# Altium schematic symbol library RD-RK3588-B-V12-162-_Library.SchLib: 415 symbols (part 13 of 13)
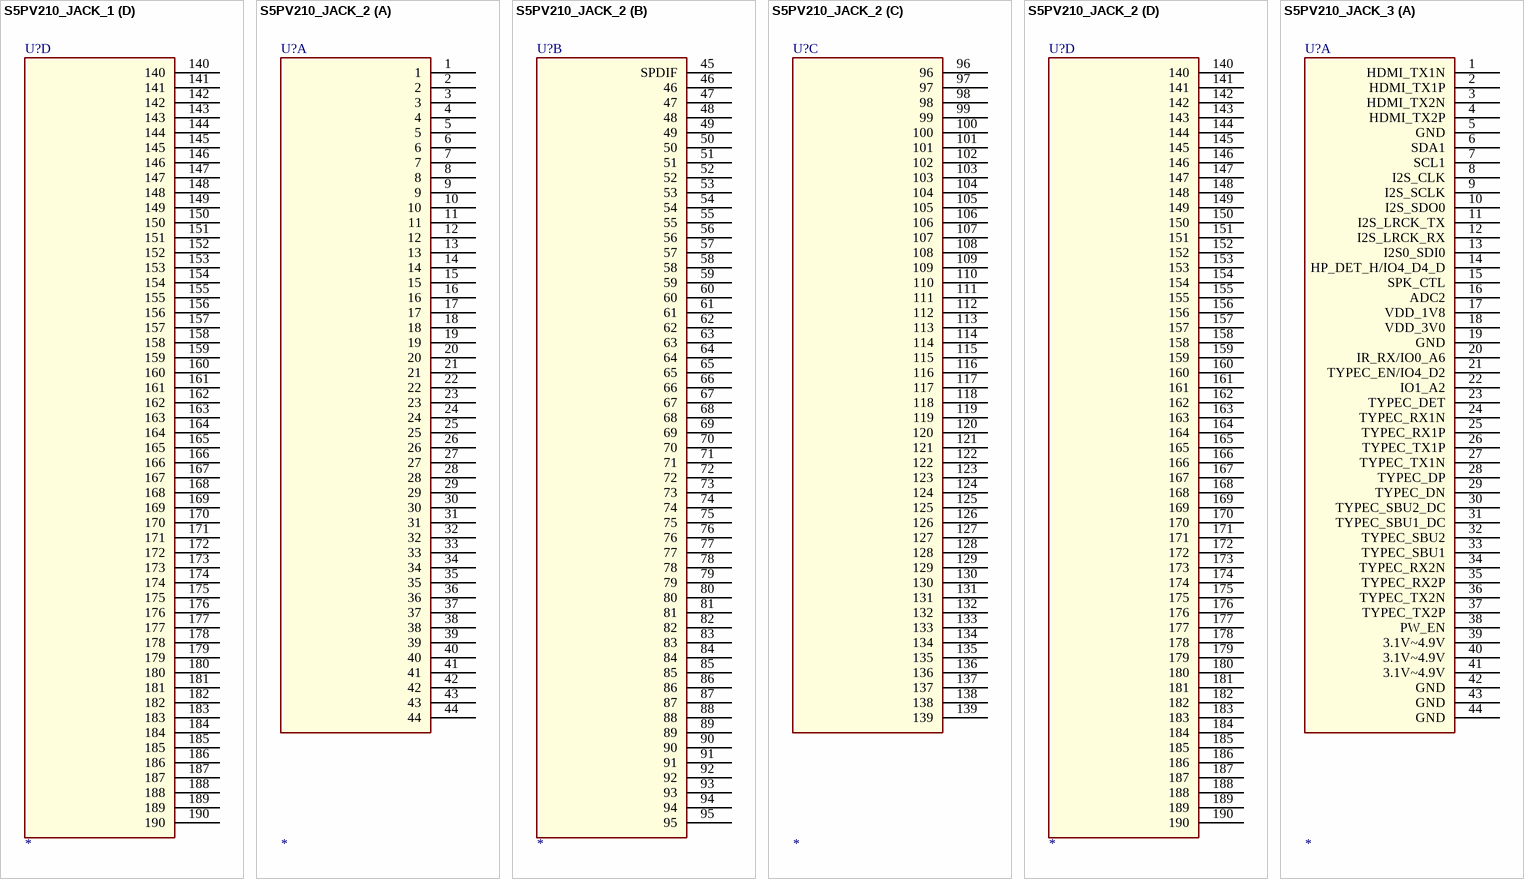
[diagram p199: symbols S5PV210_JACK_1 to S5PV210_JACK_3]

## S5PV210_JACK_1
designator U?
footprint S5PV210_JACK
part A pins: 1, 2, 3, 4, 5, 6, 7, 8, 9, 10, 11, 12, 13, 14, 15, 16, 17, 18, 19, 20, 21, 22, 23, 24, 25, 26, 27, 28, 29, 30, 31, 32, 33, 34, 35, 36, 37, 38, 39, 40, 41, 42, 43, 44
part B pins: 45, 46, 47, 48, 49, 50, 51, 52, 53, 54, 55, 56, 57, 58, 59, 60, 61, 62, 63, 64, 65, 66, 67, 68, 69, 70, 71, 72, 73, 74, 75, 76, 77, 78, 79, 80, 81, 82, 83, 84, 85, 86, 87, 88, 89, 90, 91, 92, 93, 94, 95
part C pins: 96, 97, 98, 99, 100, 101, 102, 103, 104, 105, 106, 107, 108, 109, 110, 111, 112, 113, 114, 115, 116, 117, 118, 119, 120, 121, 122, 123, 124, 125, 126, 127, 128, 129, 130, 131, 132, 133, 134, 135, 136, 137, 138, 139
part D pins: 140, 141, 142, 143, 144, 145, 146, 147, 148, 149, 150, 151, 152, 153, 154, 155, 156, 157, 158, 159, 160, 161, 162, 163, 164, 165, 166, 167, 168, 169, 170, 171, 172, 173, 174, 175, 176, 177, 178, 179, 180, 181, 182, 183, 184, 185, 186, 187, 188, 189, 190

## S5PV210_JACK_2
designator U?
footprint S5PV210_JACK
part A pins: 1, 2, 3, 4, 5, 6, 7, 8, 9, 10, 11, 12, 13, 14, 15, 16, 17, 18, 19, 20, 21, 22, 23, 24, 25, 26, 27, 28, 29, 30, 31, 32, 33, 34, 35, 36, 37, 38, 39, 40, 41, 42, 43, 44
part B pins: 45 SPDIF, 46, 47, 48, 49, 50, 51, 52, 53, 54, 55, 56, 57, 58, 59, 60, 61, 62, 63, 64, 65, 66, 67, 68, 69, 70, 71, 72, 73, 74, 75, 76, 77, 78, 79, 80, 81, 82, 83, 84, 85, 86, 87, 88, 89, 90, 91, 92, 93, 94, 95
part C pins: 96, 97, 98, 99, 100, 101, 102, 103, 104, 105, 106, 107, 108, 109, 110, 111, 112, 113, 114, 115, 116, 117, 118, 119, 120, 121, 122, 123, 124, 125, 126, 127, 128, 129, 130, 131, 132, 133, 134, 135, 136, 137, 138, 139
part D pins: 140, 141, 142, 143, 144, 145, 146, 147, 148, 149, 150, 151, 152, 153, 154, 155, 156, 157, 158, 159, 160, 161, 162, 163, 164, 165, 166, 167, 168, 169, 170, 171, 172, 173, 174, 175, 176, 177, 178, 179, 180, 181, 182, 183, 184, 185, 186, 187, 188, 189, 190

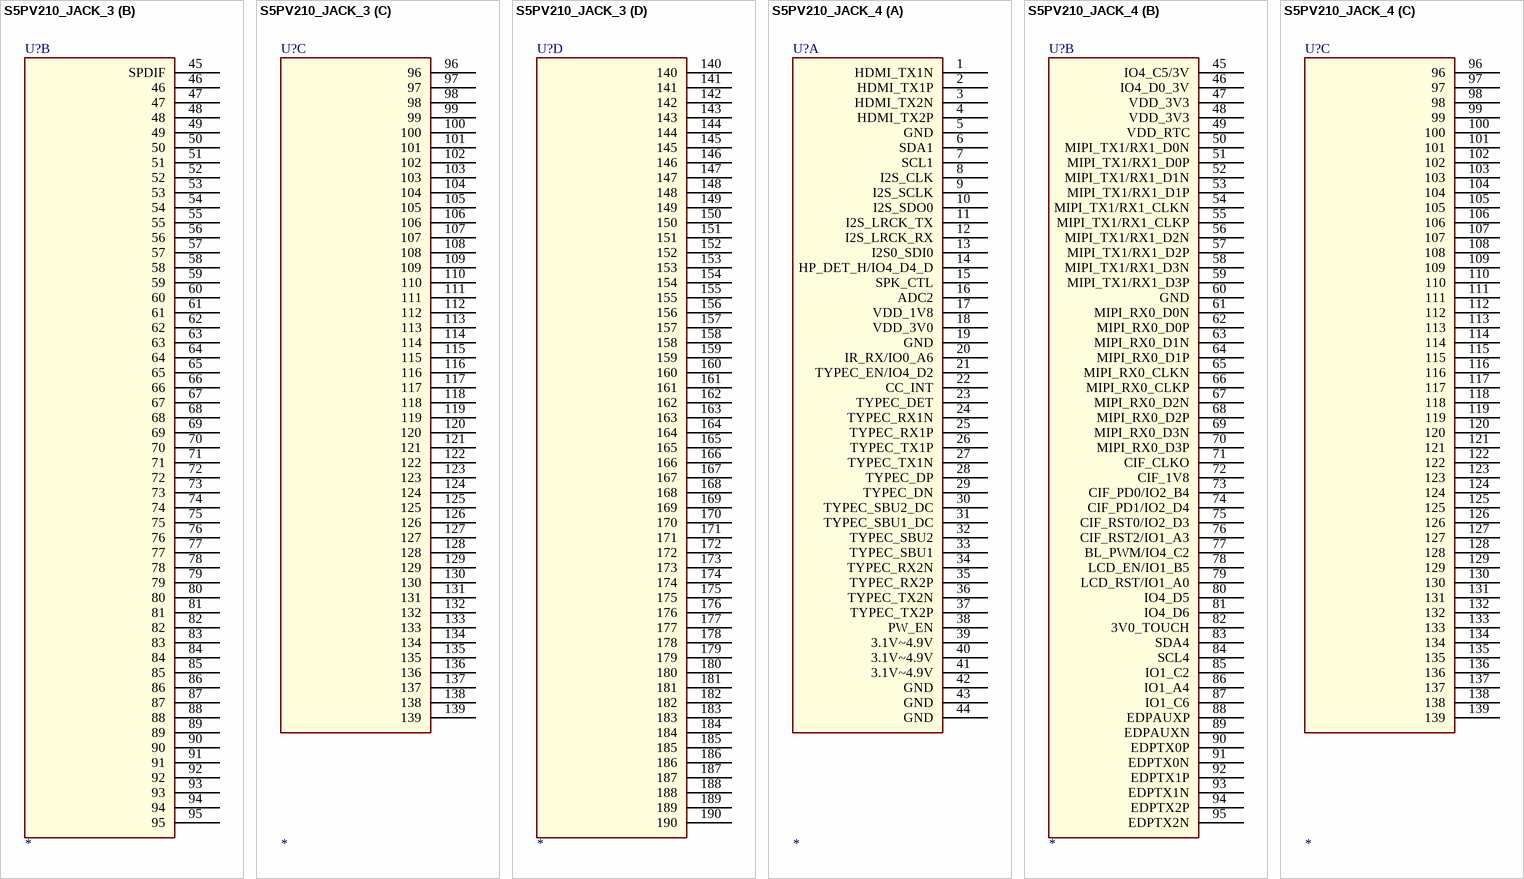
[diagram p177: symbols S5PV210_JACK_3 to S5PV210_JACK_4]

## S5PV210_JACK_3
designator U?
footprint S5PV210_JACK
part A pins: 1 HDMI_TX1N, 2 HDMI_TX1P, 3 HDMI_TX2N, 4 HDMI_TX2P, 5 GND (power), 6 SDA1, 7 SCL1, 8 I2S_CLK, 9 I2S_SCLK, 10 I2S_SDO0, 11 I2S_LRCK_TX, 12 I2S_LRCK_RX, 13 I2S0_SDI0, 14 HP_DET_H/IO4_D4_D, 15 SPK_CTL, 16 ADC2, 17 VDD_1V8, 18 VDD_3V0, 19 GND (power), 20 IR_RX/IO0_A6, 21 TYPEC_EN/IO4_D2, 22 IO1_A2, 23 TYPEC_DET, 24 TYPEC_RX1N, 25 TYPEC_RX1P, 26 TYPEC_TX1P, 27 TYPEC_TX1N, 28 TYPEC_DP, 29 TYPEC_DN, 30 TYPEC_SBU2_DC, 31 TYPEC_SBU1_DC, 32 TYPEC_SBU2, 33 TYPEC_SBU1, 34 TYPEC_RX2N, 35 TYPEC_RX2P, 36 TYPEC_TX2N, 37 TYPEC_TX2P, 38 PW_EN, 39 3.1V~4.9V (power), 40 3.1V~4.9V (power), 41 3.1V~4.9V (power), 42 GND (power), 43 GND (power), 44 GND (power)
part B pins: 45 SPDIF, 46, 47, 48, 49, 50, 51, 52, 53, 54, 55, 56, 57, 58, 59, 60, 61, 62, 63, 64, 65, 66, 67, 68, 69, 70, 71, 72, 73, 74, 75, 76, 77, 78, 79, 80, 81, 82, 83, 84, 85, 86, 87, 88, 89, 90, 91, 92, 93, 94, 95
part C pins: 96, 97, 98, 99, 100, 101, 102, 103, 104, 105, 106, 107, 108, 109, 110, 111, 112, 113, 114, 115, 116, 117, 118, 119, 120, 121, 122, 123, 124, 125, 126, 127, 128, 129, 130, 131, 132, 133, 134, 135, 136, 137, 138, 139
part D pins: 140, 141, 142, 143, 144, 145, 146, 147, 148, 149, 150, 151, 152, 153, 154, 155, 156, 157, 158, 159, 160, 161, 162, 163, 164, 165, 166, 167, 168, 169, 170, 171, 172, 173, 174, 175, 176, 177, 178, 179, 180, 181, 182, 183, 184, 185, 186, 187, 188, 189, 190

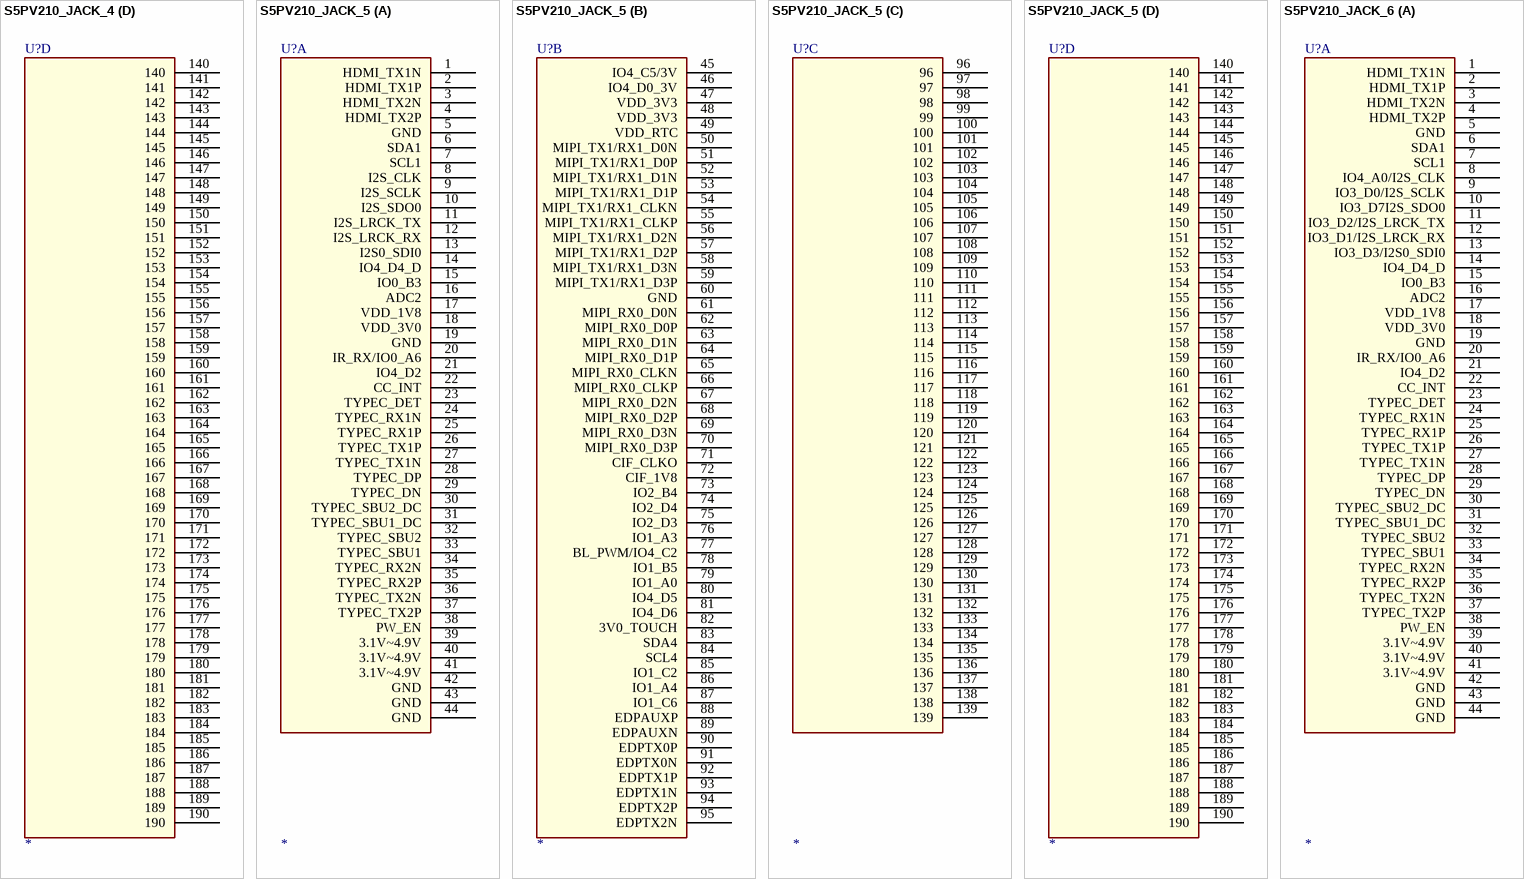
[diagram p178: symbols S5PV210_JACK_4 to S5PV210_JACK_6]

## S5PV210_JACK_4
designator U?
footprint S5PV210_JACK
part A pins: 1 HDMI_TX1N, 2 HDMI_TX1P, 3 HDMI_TX2N, 4 HDMI_TX2P, 5 GND (power), 6 SDA1, 7 SCL1, 8 I2S_CLK, 9 I2S_SCLK, 10 I2S_SDO0, 11 I2S_LRCK_TX, 12 I2S_LRCK_RX, 13 I2S0_SDI0, 14 HP_DET_H/IO4_D4_D, 15 SPK_CTL, 16 ADC2, 17 VDD_1V8, 18 VDD_3V0, 19 GND (power), 20 IR_RX/IO0_A6, 21 TYPEC_EN/IO4_D2, 22 CC_INT, 23 TYPEC_DET, 24 TYPEC_RX1N, 25 TYPEC_RX1P, 26 TYPEC_TX1P, 27 TYPEC_TX1N, 28 TYPEC_DP, 29 TYPEC_DN, 30 TYPEC_SBU2_DC, 31 TYPEC_SBU1_DC, 32 TYPEC_SBU2, 33 TYPEC_SBU1, 34 TYPEC_RX2N, 35 TYPEC_RX2P, 36 TYPEC_TX2N, 37 TYPEC_TX2P, 38 PW_EN, 39 3.1V~4.9V (power), 40 3.1V~4.9V (power), 41 3.1V~4.9V (power), 42 GND (power), 43 GND (power), 44 GND (power)
part B pins: 45 IO4_C5/3V, 46 IO4_D0_3V, 47 VDD_3V3 (power), 48 VDD_3V3 (power), 49 VDD_RTC, 50 MIPI_TX1/RX1_D0N, 51 MIPI_TX1/RX1_D0P, 52 MIPI_TX1/RX1_D1N, 53 MIPI_TX1/RX1_D1P, 54 MIPI_TX1/RX1_CLKN, 55 MIPI_TX1/RX1_CLKP, 56 MIPI_TX1/RX1_D2N, 57 MIPI_TX1/RX1_D2P, 58 MIPI_TX1/RX1_D3N, 59 MIPI_TX1/RX1_D3P, 60 GND, 61 MIPI_RX0_D0N, 62 MIPI_RX0_D0P, 63 MIPI_RX0_D1N, 64 MIPI_RX0_D1P, 65 MIPI_RX0_CLKN, 66 MIPI_RX0_CLKP, 67 MIPI_RX0_D2N, 68 MIPI_RX0_D2P, 69 MIPI_RX0_D3N, 70 MIPI_RX0_D3P, 71 CIF_CLKO, 72 CIF_1V8, 73 CIF_PD0/IO2_B4, 74 CIF_PD1/IO2_D4, 75 CIF_RST0/IO2_D3, 76 CIF_RST2/IO1_A3, 77 BL_PWM/IO4_C2, 78 LCD_EN/IO1_B5, 79 LCD_RST/IO1_A0, 80 IO4_D5, 81 IO4_D6, 82 3V0_TOUCH, 83 SDA4, 84 SCL4, 85 IO1_C2, 86 IO1_A4, 87 IO1_C6, 88 EDPAUXP, 89 EDPAUXN, 90 EDPTX0P, 91 EDPTX0N, 92 EDPTX1P, 93 EDPTX1N, 94 EDPTX2P, 95 EDPTX2N
part C pins: 96, 97, 98, 99, 100, 101, 102, 103, 104, 105, 106, 107, 108, 109, 110, 111, 112, 113, 114, 115, 116, 117, 118, 119, 120, 121, 122, 123, 124, 125, 126, 127, 128, 129, 130, 131, 132, 133, 134, 135, 136, 137, 138, 139
part D pins: 140, 141, 142, 143, 144, 145, 146, 147, 148, 149, 150, 151, 152, 153, 154, 155, 156, 157, 158, 159, 160, 161, 162, 163, 164, 165, 166, 167, 168, 169, 170, 171, 172, 173, 174, 175, 176, 177, 178, 179, 180, 181, 182, 183, 184, 185, 186, 187, 188, 189, 190

## S5PV210_JACK_5
designator U?
footprint S5PV210_JACK
part A pins: 1 HDMI_TX1N, 2 HDMI_TX1P, 3 HDMI_TX2N, 4 HDMI_TX2P, 5 GND (power), 6 SDA1, 7 SCL1, 8 I2S_CLK, 9 I2S_SCLK, 10 I2S_SDO0, 11 I2S_LRCK_TX, 12 I2S_LRCK_RX, 13 I2S0_SDI0, 14 IO4_D4_D, 15 IO0_B3, 16 ADC2, 17 VDD_1V8, 18 VDD_3V0, 19 GND (power), 20 IR_RX/IO0_A6, 21 IO4_D2, 22 CC_INT, 23 TYPEC_DET, 24 TYPEC_RX1N, 25 TYPEC_RX1P, 26 TYPEC_TX1P, 27 TYPEC_TX1N, 28 TYPEC_DP, 29 TYPEC_DN, 30 TYPEC_SBU2_DC, 31 TYPEC_SBU1_DC, 32 TYPEC_SBU2, 33 TYPEC_SBU1, 34 TYPEC_RX2N, 35 TYPEC_RX2P, 36 TYPEC_TX2N, 37 TYPEC_TX2P, 38 PW_EN, 39 3.1V~4.9V (power), 40 3.1V~4.9V (power), 41 3.1V~4.9V (power), 42 GND (power), 43 GND (power), 44 GND (power)
part B pins: 45 IO4_C5/3V, 46 IO4_D0_3V, 47 VDD_3V3 (power), 48 VDD_3V3 (power), 49 VDD_RTC, 50 MIPI_TX1/RX1_D0N, 51 MIPI_TX1/RX1_D0P, 52 MIPI_TX1/RX1_D1N, 53 MIPI_TX1/RX1_D1P, 54 MIPI_TX1/RX1_CLKN, 55 MIPI_TX1/RX1_CLKP, 56 MIPI_TX1/RX1_D2N, 57 MIPI_TX1/RX1_D2P, 58 MIPI_TX1/RX1_D3N, 59 MIPI_TX1/RX1_D3P, 60 GND, 61 MIPI_RX0_D0N, 62 MIPI_RX0_D0P, 63 MIPI_RX0_D1N, 64 MIPI_RX0_D1P, 65 MIPI_RX0_CLKN, 66 MIPI_RX0_CLKP, 67 MIPI_RX0_D2N, 68 MIPI_RX0_D2P, 69 MIPI_RX0_D3N, 70 MIPI_RX0_D3P, 71 CIF_CLKO, 72 CIF_1V8, 73 IO2_B4, 74 IO2_D4, 75 IO2_D3, 76 IO1_A3, 77 BL_PWM/IO4_C2, 78 IO1_B5, 79 IO1_A0, 80 IO4_D5, 81 IO4_D6, 82 3V0_TOUCH, 83 SDA4, 84 SCL4, 85 IO1_C2, 86 IO1_A4, 87 IO1_C6, 88 EDPAUXP, 89 EDPAUXN, 90 EDPTX0P, 91 EDPTX0N, 92 EDPTX1P, 93 EDPTX1N, 94 EDPTX2P, 95 EDPTX2N
part C pins: 96, 97, 98, 99, 100, 101, 102, 103, 104, 105, 106, 107, 108, 109, 110, 111, 112, 113, 114, 115, 116, 117, 118, 119, 120, 121, 122, 123, 124, 125, 126, 127, 128, 129, 130, 131, 132, 133, 134, 135, 136, 137, 138, 139
part D pins: 140, 141, 142, 143, 144, 145, 146, 147, 148, 149, 150, 151, 152, 153, 154, 155, 156, 157, 158, 159, 160, 161, 162, 163, 164, 165, 166, 167, 168, 169, 170, 171, 172, 173, 174, 175, 176, 177, 178, 179, 180, 181, 182, 183, 184, 185, 186, 187, 188, 189, 190

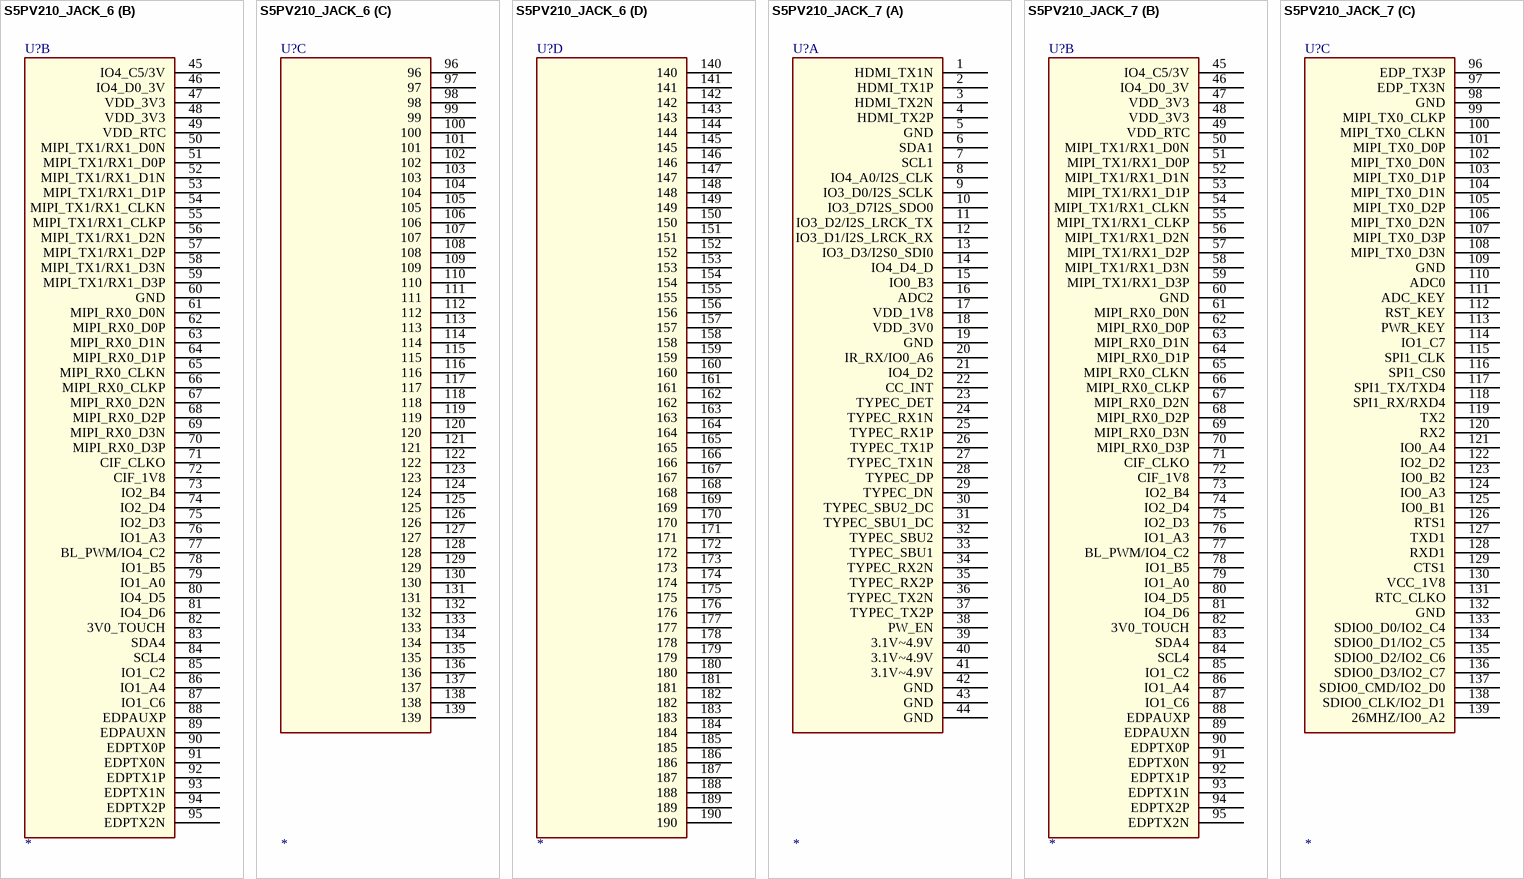
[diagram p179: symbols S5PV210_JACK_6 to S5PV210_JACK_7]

## S5PV210_JACK_6
designator U?
footprint S5PV210_JACK
part A pins: 1 HDMI_TX1N, 2 HDMI_TX1P, 3 HDMI_TX2N, 4 HDMI_TX2P, 5 GND (power), 6 SDA1, 7 SCL1, 8 IO4_A0/I2S_CLK, 9 IO3_D0/I2S_SCLK, 10 IO3_D7I2S_SDO0, 11 IO3_D2/I2S_LRCK_TX, 12 IO3_D1/I2S_LRCK_RX, 13 IO3_D3/I2S0_SDI0, 14 IO4_D4_D, 15 IO0_B3, 16 ADC2, 17 VDD_1V8, 18 VDD_3V0, 19 GND (power), 20 IR_RX/IO0_A6, 21 IO4_D2, 22 CC_INT, 23 TYPEC_DET, 24 TYPEC_RX1N, 25 TYPEC_RX1P, 26 TYPEC_TX1P, 27 TYPEC_TX1N, 28 TYPEC_DP, 29 TYPEC_DN, 30 TYPEC_SBU2_DC, 31 TYPEC_SBU1_DC, 32 TYPEC_SBU2, 33 TYPEC_SBU1, 34 TYPEC_RX2N, 35 TYPEC_RX2P, 36 TYPEC_TX2N, 37 TYPEC_TX2P, 38 PW_EN, 39 3.1V~4.9V (power), 40 3.1V~4.9V (power), 41 3.1V~4.9V (power), 42 GND (power), 43 GND (power), 44 GND (power)
part B pins: 45 IO4_C5/3V, 46 IO4_D0_3V, 47 VDD_3V3 (power), 48 VDD_3V3 (power), 49 VDD_RTC, 50 MIPI_TX1/RX1_D0N, 51 MIPI_TX1/RX1_D0P, 52 MIPI_TX1/RX1_D1N, 53 MIPI_TX1/RX1_D1P, 54 MIPI_TX1/RX1_CLKN, 55 MIPI_TX1/RX1_CLKP, 56 MIPI_TX1/RX1_D2N, 57 MIPI_TX1/RX1_D2P, 58 MIPI_TX1/RX1_D3N, 59 MIPI_TX1/RX1_D3P, 60 GND, 61 MIPI_RX0_D0N, 62 MIPI_RX0_D0P, 63 MIPI_RX0_D1N, 64 MIPI_RX0_D1P, 65 MIPI_RX0_CLKN, 66 MIPI_RX0_CLKP, 67 MIPI_RX0_D2N, 68 MIPI_RX0_D2P, 69 MIPI_RX0_D3N, 70 MIPI_RX0_D3P, 71 CIF_CLKO, 72 CIF_1V8, 73 IO2_B4, 74 IO2_D4, 75 IO2_D3, 76 IO1_A3, 77 BL_PWM/IO4_C2, 78 IO1_B5, 79 IO1_A0, 80 IO4_D5, 81 IO4_D6, 82 3V0_TOUCH, 83 SDA4, 84 SCL4, 85 IO1_C2, 86 IO1_A4, 87 IO1_C6, 88 EDPAUXP, 89 EDPAUXN, 90 EDPTX0P, 91 EDPTX0N, 92 EDPTX1P, 93 EDPTX1N, 94 EDPTX2P, 95 EDPTX2N
part C pins: 96, 97, 98, 99, 100, 101, 102, 103, 104, 105, 106, 107, 108, 109, 110, 111, 112, 113, 114, 115, 116, 117, 118, 119, 120, 121, 122, 123, 124, 125, 126, 127, 128, 129, 130, 131, 132, 133, 134, 135, 136, 137, 138, 139
part D pins: 140, 141, 142, 143, 144, 145, 146, 147, 148, 149, 150, 151, 152, 153, 154, 155, 156, 157, 158, 159, 160, 161, 162, 163, 164, 165, 166, 167, 168, 169, 170, 171, 172, 173, 174, 175, 176, 177, 178, 179, 180, 181, 182, 183, 184, 185, 186, 187, 188, 189, 190

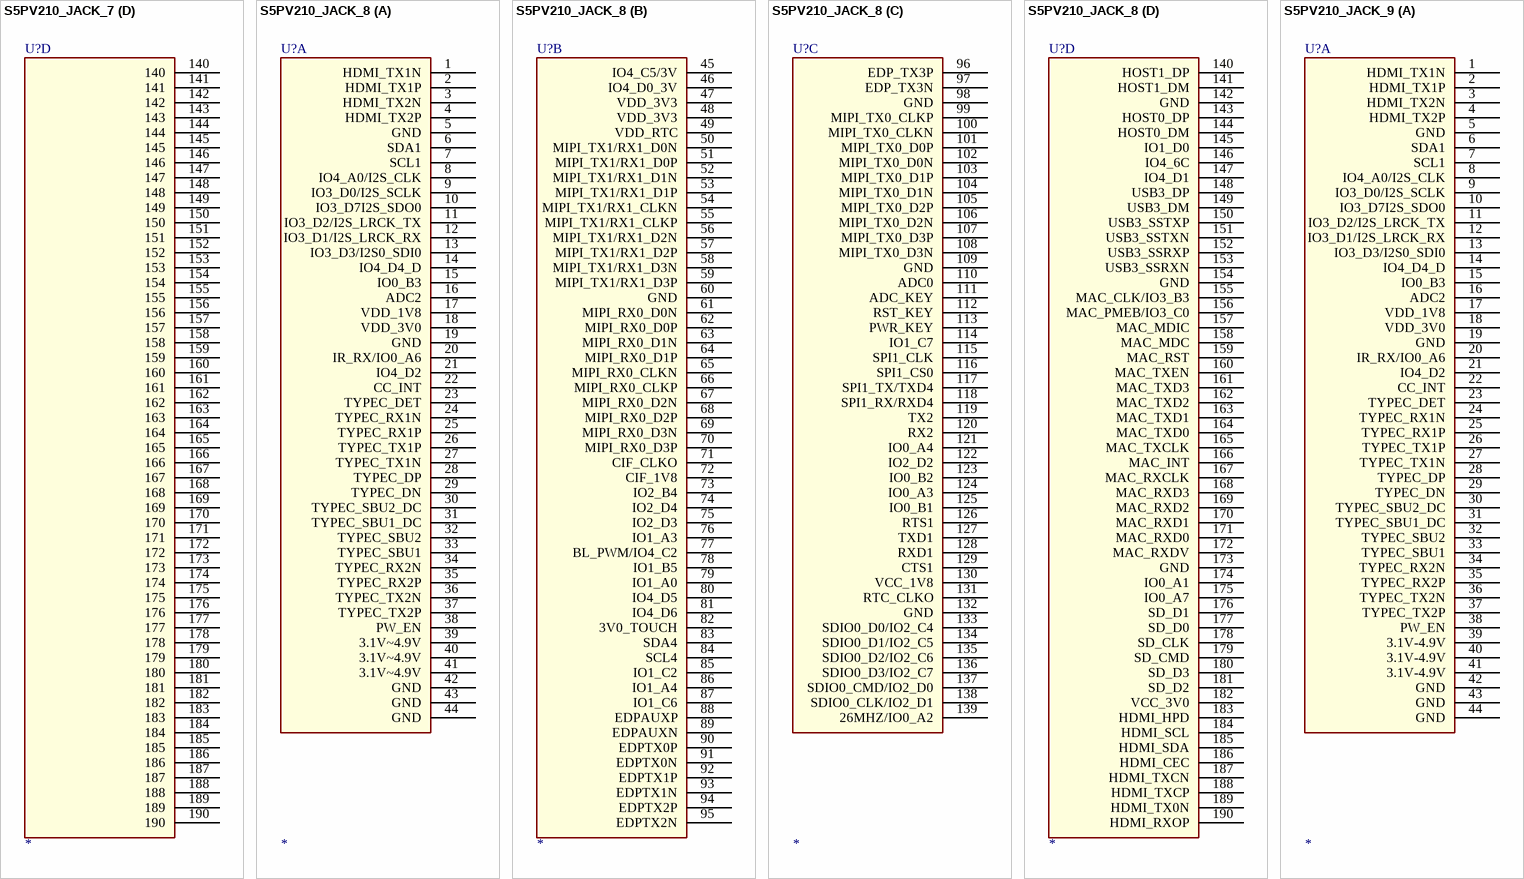
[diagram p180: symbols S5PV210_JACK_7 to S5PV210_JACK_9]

## S5PV210_JACK_7
designator U?
footprint S5PV210_JACK
part A pins: 1 HDMI_TX1N, 2 HDMI_TX1P, 3 HDMI_TX2N, 4 HDMI_TX2P, 5 GND (power), 6 SDA1, 7 SCL1, 8 IO4_A0/I2S_CLK, 9 IO3_D0/I2S_SCLK, 10 IO3_D7I2S_SDO0, 11 IO3_D2/I2S_LRCK_TX, 12 IO3_D1/I2S_LRCK_RX, 13 IO3_D3/I2S0_SDI0, 14 IO4_D4_D, 15 IO0_B3, 16 ADC2, 17 VDD_1V8, 18 VDD_3V0, 19 GND (power), 20 IR_RX/IO0_A6, 21 IO4_D2, 22 CC_INT, 23 TYPEC_DET, 24 TYPEC_RX1N, 25 TYPEC_RX1P, 26 TYPEC_TX1P, 27 TYPEC_TX1N, 28 TYPEC_DP, 29 TYPEC_DN, 30 TYPEC_SBU2_DC, 31 TYPEC_SBU1_DC, 32 TYPEC_SBU2, 33 TYPEC_SBU1, 34 TYPEC_RX2N, 35 TYPEC_RX2P, 36 TYPEC_TX2N, 37 TYPEC_TX2P, 38 PW_EN, 39 3.1V~4.9V (power), 40 3.1V~4.9V (power), 41 3.1V~4.9V (power), 42 GND (power), 43 GND (power), 44 GND (power)
part B pins: 45 IO4_C5/3V, 46 IO4_D0_3V, 47 VDD_3V3 (power), 48 VDD_3V3 (power), 49 VDD_RTC, 50 MIPI_TX1/RX1_D0N, 51 MIPI_TX1/RX1_D0P, 52 MIPI_TX1/RX1_D1N, 53 MIPI_TX1/RX1_D1P, 54 MIPI_TX1/RX1_CLKN, 55 MIPI_TX1/RX1_CLKP, 56 MIPI_TX1/RX1_D2N, 57 MIPI_TX1/RX1_D2P, 58 MIPI_TX1/RX1_D3N, 59 MIPI_TX1/RX1_D3P, 60 GND, 61 MIPI_RX0_D0N, 62 MIPI_RX0_D0P, 63 MIPI_RX0_D1N, 64 MIPI_RX0_D1P, 65 MIPI_RX0_CLKN, 66 MIPI_RX0_CLKP, 67 MIPI_RX0_D2N, 68 MIPI_RX0_D2P, 69 MIPI_RX0_D3N, 70 MIPI_RX0_D3P, 71 CIF_CLKO, 72 CIF_1V8, 73 IO2_B4, 74 IO2_D4, 75 IO2_D3, 76 IO1_A3, 77 BL_PWM/IO4_C2, 78 IO1_B5, 79 IO1_A0, 80 IO4_D5, 81 IO4_D6, 82 3V0_TOUCH, 83 SDA4, 84 SCL4, 85 IO1_C2, 86 IO1_A4, 87 IO1_C6, 88 EDPAUXP, 89 EDPAUXN, 90 EDPTX0P, 91 EDPTX0N, 92 EDPTX1P, 93 EDPTX1N, 94 EDPTX2P, 95 EDPTX2N
part C pins: 96 EDP_TX3P, 97 EDP_TX3N, 98 GND (power), 99 MIPI_TX0_CLKP, 100 MIPI_TX0_CLKN, 101 MIPI_TX0_D0P, 102 MIPI_TX0_D0N, 103 MIPI_TX0_D1P, 104 MIPI_TX0_D1N, 105 MIPI_TX0_D2P, 106 MIPI_TX0_D2N, 107 MIPI_TX0_D3P, 108 MIPI_TX0_D3N, 109 GND (power), 110 ADC0, 111 ADC_KEY, 112 RST_KEY, 113 PWR_KEY, 114 IO1_C7, 115 SPI1_CLK, 116 SPI1_CS0, 117 SPI1_TX/TXD4, 118 SPI1_RX/RXD4, 119 TX2, 120 RX2, 121 IO0_A4, 122 IO2_D2, 123 IO0_B2, 124 IO0_A3, 125 IO0_B1, 126 RTS1, 127 TXD1, 128 RXD1, 129 CTS1, 130 VCC_1V8, 131 RTC_CLKO, 132 GND (power), 133 SDIO0_D0/IO2_C4, 134 SDIO0_D1/IO2_C5, 135 SDIO0_D2/IO2_C6, 136 SDIO0_D3/IO2_C7, 137 SDIO0_CMD/IO2_D0, 138 SDIO0_CLK/IO2_D1, 139 26MHZ/IO0_A2
part D pins: 140, 141, 142, 143, 144, 145, 146, 147, 148, 149, 150, 151, 152, 153, 154, 155, 156, 157, 158, 159, 160, 161, 162, 163, 164, 165, 166, 167, 168, 169, 170, 171, 172, 173, 174, 175, 176, 177, 178, 179, 180, 181, 182, 183, 184, 185, 186, 187, 188, 189, 190

## S5PV210_JACK_8
designator U?
footprint S5PV210_JACK
part A pins: 1 HDMI_TX1N, 2 HDMI_TX1P, 3 HDMI_TX2N, 4 HDMI_TX2P, 5 GND (power), 6 SDA1, 7 SCL1, 8 IO4_A0/I2S_CLK, 9 IO3_D0/I2S_SCLK, 10 IO3_D7I2S_SDO0, 11 IO3_D2/I2S_LRCK_TX, 12 IO3_D1/I2S_LRCK_RX, 13 IO3_D3/I2S0_SDI0, 14 IO4_D4_D, 15 IO0_B3, 16 ADC2, 17 VDD_1V8, 18 VDD_3V0, 19 GND (power), 20 IR_RX/IO0_A6, 21 IO4_D2, 22 CC_INT, 23 TYPEC_DET, 24 TYPEC_RX1N, 25 TYPEC_RX1P, 26 TYPEC_TX1P, 27 TYPEC_TX1N, 28 TYPEC_DP, 29 TYPEC_DN, 30 TYPEC_SBU2_DC, 31 TYPEC_SBU1_DC, 32 TYPEC_SBU2, 33 TYPEC_SBU1, 34 TYPEC_RX2N, 35 TYPEC_RX2P, 36 TYPEC_TX2N, 37 TYPEC_TX2P, 38 PW_EN, 39 3.1V~4.9V (power), 40 3.1V~4.9V (power), 41 3.1V~4.9V (power), 42 GND (power), 43 GND (power), 44 GND (power)
part B pins: 45 IO4_C5/3V, 46 IO4_D0_3V, 47 VDD_3V3 (power), 48 VDD_3V3 (power), 49 VDD_RTC, 50 MIPI_TX1/RX1_D0N, 51 MIPI_TX1/RX1_D0P, 52 MIPI_TX1/RX1_D1N, 53 MIPI_TX1/RX1_D1P, 54 MIPI_TX1/RX1_CLKN, 55 MIPI_TX1/RX1_CLKP, 56 MIPI_TX1/RX1_D2N, 57 MIPI_TX1/RX1_D2P, 58 MIPI_TX1/RX1_D3N, 59 MIPI_TX1/RX1_D3P, 60 GND, 61 MIPI_RX0_D0N, 62 MIPI_RX0_D0P, 63 MIPI_RX0_D1N, 64 MIPI_RX0_D1P, 65 MIPI_RX0_CLKN, 66 MIPI_RX0_CLKP, 67 MIPI_RX0_D2N, 68 MIPI_RX0_D2P, 69 MIPI_RX0_D3N, 70 MIPI_RX0_D3P, 71 CIF_CLKO, 72 CIF_1V8, 73 IO2_B4, 74 IO2_D4, 75 IO2_D3, 76 IO1_A3, 77 BL_PWM/IO4_C2, 78 IO1_B5, 79 IO1_A0, 80 IO4_D5, 81 IO4_D6, 82 3V0_TOUCH, 83 SDA4, 84 SCL4, 85 IO1_C2, 86 IO1_A4, 87 IO1_C6, 88 EDPAUXP, 89 EDPAUXN, 90 EDPTX0P, 91 EDPTX0N, 92 EDPTX1P, 93 EDPTX1N, 94 EDPTX2P, 95 EDPTX2N
part C pins: 96 EDP_TX3P, 97 EDP_TX3N, 98 GND (power), 99 MIPI_TX0_CLKP, 100 MIPI_TX0_CLKN, 101 MIPI_TX0_D0P, 102 MIPI_TX0_D0N, 103 MIPI_TX0_D1P, 104 MIPI_TX0_D1N, 105 MIPI_TX0_D2P, 106 MIPI_TX0_D2N, 107 MIPI_TX0_D3P, 108 MIPI_TX0_D3N, 109 GND (power), 110 ADC0, 111 ADC_KEY, 112 RST_KEY, 113 PWR_KEY, 114 IO1_C7, 115 SPI1_CLK, 116 SPI1_CS0, 117 SPI1_TX/TXD4, 118 SPI1_RX/RXD4, 119 TX2, 120 RX2, 121 IO0_A4, 122 IO2_D2, 123 IO0_B2, 124 IO0_A3, 125 IO0_B1, 126 RTS1, 127 TXD1, 128 RXD1, 129 CTS1, 130 VCC_1V8, 131 RTC_CLKO, 132 GND (power), 133 SDIO0_D0/IO2_C4, 134 SDIO0_D1/IO2_C5, 135 SDIO0_D2/IO2_C6, 136 SDIO0_D3/IO2_C7, 137 SDIO0_CMD/IO2_D0, 138 SDIO0_CLK/IO2_D1, 139 26MHZ/IO0_A2
part D pins: 140 HOST1_DP, 141 HOST1_DM, 142 GND (power), 143 HOST0_DP, 144 HOST0_DM, 145 IO1_D0, 146 IO4_6C, 147 IO4_D1, 148 USB3_DP, 149 USB3_DM, 150 USB3_SSTXP, 151 USB3_SSTXN, 152 USB3_SSRXP, 153 USB3_SSRXN, 154 GND (power), 155 MAC_CLK/IO3_B3, 156 MAC_PMEB/IO3_C0, 157 MAC_MDIC, 158 MAC_MDC, 159 MAC_RST, 160 MAC_TXEN, 161 MAC_TXD3, 162 MAC_TXD2, 163 MAC_TXD1, 164 MAC_TXD0, 165 MAC_TXCLK, 166 MAC_INT, 167 MAC_RXCLK, 168 MAC_RXD3, 169 MAC_RXD2, 170 MAC_RXD1, 171 MAC_RXD0, 172 MAC_RXDV, 173 GND (power), 174 IO0_A1, 175 IO0_A7, 176 SD_D1, 177 SD_D0, 178 SD_CLK, 179 SD_CMD, 180 SD_D3, 181 SD_D2, 182 VCC_3V0, 183 HDMI_HPD, 184 HDMI_SCL, 185 HDMI_SDA, 186 HDMI_CEC, 187 HDMI_TXCN, 188 HDMI_TXCP, 189 HDMI_TX0N, 190 HDMI_RXOP

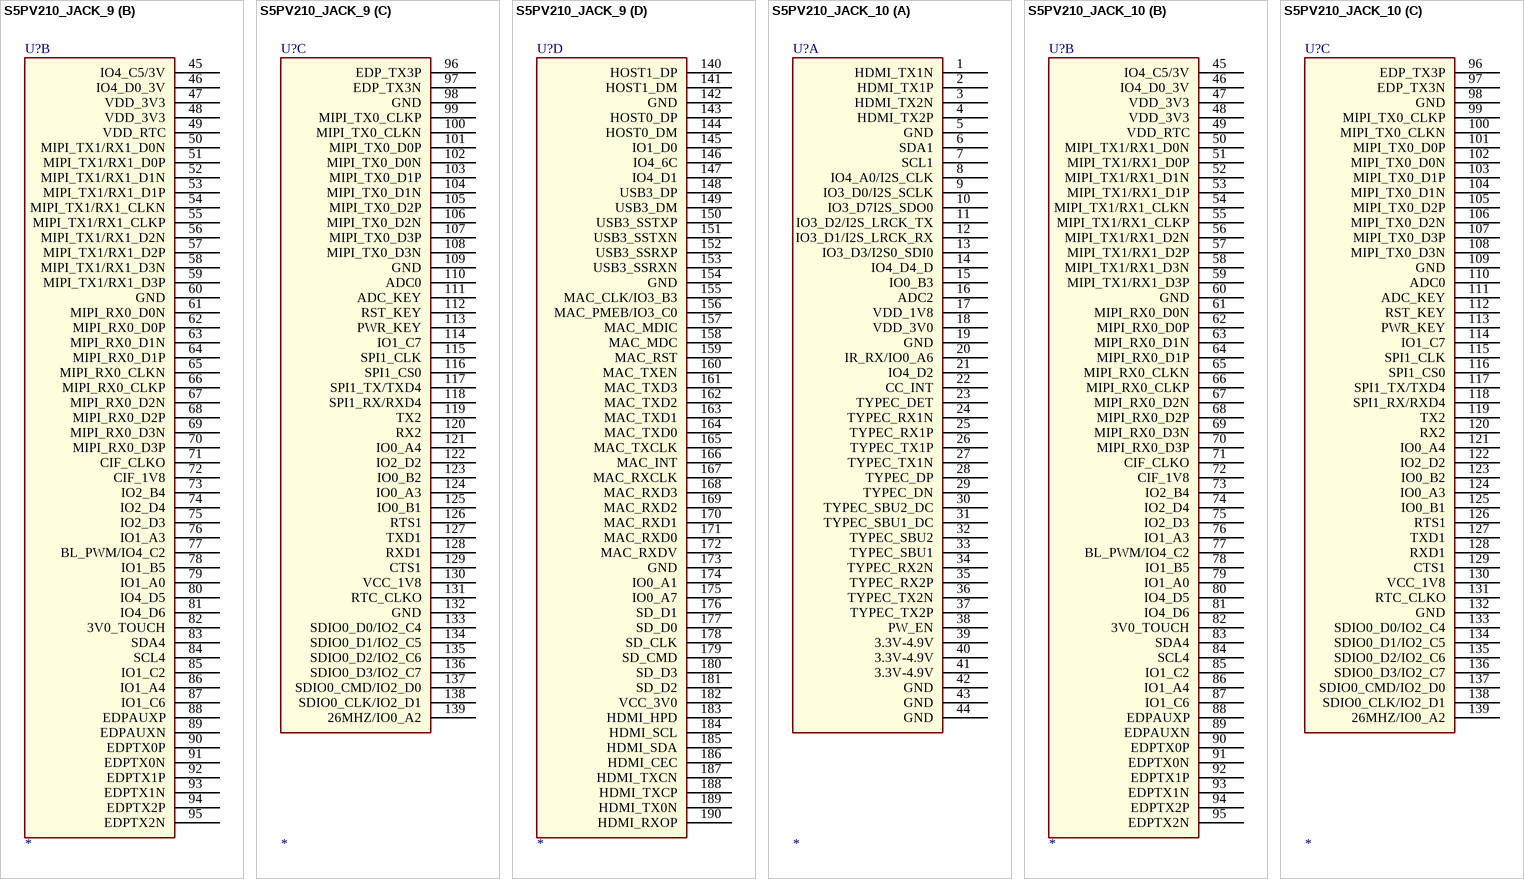
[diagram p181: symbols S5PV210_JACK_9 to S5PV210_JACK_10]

## S5PV210_JACK_9
designator U?
footprint S5PV210_JACK
part A pins: 1 HDMI_TX1N, 2 HDMI_TX1P, 3 HDMI_TX2N, 4 HDMI_TX2P, 5 GND (power), 6 SDA1, 7 SCL1, 8 IO4_A0/I2S_CLK, 9 IO3_D0/I2S_SCLK, 10 IO3_D7I2S_SDO0, 11 IO3_D2/I2S_LRCK_TX, 12 IO3_D1/I2S_LRCK_RX, 13 IO3_D3/I2S0_SDI0, 14 IO4_D4_D, 15 IO0_B3, 16 ADC2, 17 VDD_1V8, 18 VDD_3V0, 19 GND (power), 20 IR_RX/IO0_A6, 21 IO4_D2, 22 CC_INT, 23 TYPEC_DET, 24 TYPEC_RX1N, 25 TYPEC_RX1P, 26 TYPEC_TX1P, 27 TYPEC_TX1N, 28 TYPEC_DP, 29 TYPEC_DN, 30 TYPEC_SBU2_DC, 31 TYPEC_SBU1_DC, 32 TYPEC_SBU2, 33 TYPEC_SBU1, 34 TYPEC_RX2N, 35 TYPEC_RX2P, 36 TYPEC_TX2N, 37 TYPEC_TX2P, 38 PW_EN, 39 3.1V-4.9V (power), 40 3.1V-4.9V (power), 41 3.1V-4.9V (power), 42 GND (power), 43 GND (power), 44 GND (power)
part B pins: 45 IO4_C5/3V, 46 IO4_D0_3V, 47 VDD_3V3 (power), 48 VDD_3V3 (power), 49 VDD_RTC, 50 MIPI_TX1/RX1_D0N, 51 MIPI_TX1/RX1_D0P, 52 MIPI_TX1/RX1_D1N, 53 MIPI_TX1/RX1_D1P, 54 MIPI_TX1/RX1_CLKN, 55 MIPI_TX1/RX1_CLKP, 56 MIPI_TX1/RX1_D2N, 57 MIPI_TX1/RX1_D2P, 58 MIPI_TX1/RX1_D3N, 59 MIPI_TX1/RX1_D3P, 60 GND, 61 MIPI_RX0_D0N, 62 MIPI_RX0_D0P, 63 MIPI_RX0_D1N, 64 MIPI_RX0_D1P, 65 MIPI_RX0_CLKN, 66 MIPI_RX0_CLKP, 67 MIPI_RX0_D2N, 68 MIPI_RX0_D2P, 69 MIPI_RX0_D3N, 70 MIPI_RX0_D3P, 71 CIF_CLKO, 72 CIF_1V8, 73 IO2_B4, 74 IO2_D4, 75 IO2_D3, 76 IO1_A3, 77 BL_PWM/IO4_C2, 78 IO1_B5, 79 IO1_A0, 80 IO4_D5, 81 IO4_D6, 82 3V0_TOUCH, 83 SDA4, 84 SCL4, 85 IO1_C2, 86 IO1_A4, 87 IO1_C6, 88 EDPAUXP, 89 EDPAUXN, 90 EDPTX0P, 91 EDPTX0N, 92 EDPTX1P, 93 EDPTX1N, 94 EDPTX2P, 95 EDPTX2N
part C pins: 96 EDP_TX3P, 97 EDP_TX3N, 98 GND (power), 99 MIPI_TX0_CLKP, 100 MIPI_TX0_CLKN, 101 MIPI_TX0_D0P, 102 MIPI_TX0_D0N, 103 MIPI_TX0_D1P, 104 MIPI_TX0_D1N, 105 MIPI_TX0_D2P, 106 MIPI_TX0_D2N, 107 MIPI_TX0_D3P, 108 MIPI_TX0_D3N, 109 GND (power), 110 ADC0, 111 ADC_KEY, 112 RST_KEY, 113 PWR_KEY, 114 IO1_C7, 115 SPI1_CLK, 116 SPI1_CS0, 117 SPI1_TX/TXD4, 118 SPI1_RX/RXD4, 119 TX2, 120 RX2, 121 IO0_A4, 122 IO2_D2, 123 IO0_B2, 124 IO0_A3, 125 IO0_B1, 126 RTS1, 127 TXD1, 128 RXD1, 129 CTS1, 130 VCC_1V8, 131 RTC_CLKO, 132 GND (power), 133 SDIO0_D0/IO2_C4, 134 SDIO0_D1/IO2_C5, 135 SDIO0_D2/IO2_C6, 136 SDIO0_D3/IO2_C7, 137 SDIO0_CMD/IO2_D0, 138 SDIO0_CLK/IO2_D1, 139 26MHZ/IO0_A2
part D pins: 140 HOST1_DP, 141 HOST1_DM, 142 GND (power), 143 HOST0_DP, 144 HOST0_DM, 145 IO1_D0, 146 IO4_6C, 147 IO4_D1, 148 USB3_DP, 149 USB3_DM, 150 USB3_SSTXP, 151 USB3_SSTXN, 152 USB3_SSRXP, 153 USB3_SSRXN, 154 GND (power), 155 MAC_CLK/IO3_B3, 156 MAC_PMEB/IO3_C0, 157 MAC_MDIC, 158 MAC_MDC, 159 MAC_RST, 160 MAC_TXEN, 161 MAC_TXD3, 162 MAC_TXD2, 163 MAC_TXD1, 164 MAC_TXD0, 165 MAC_TXCLK, 166 MAC_INT, 167 MAC_RXCLK, 168 MAC_RXD3, 169 MAC_RXD2, 170 MAC_RXD1, 171 MAC_RXD0, 172 MAC_RXDV, 173 GND (power), 174 IO0_A1, 175 IO0_A7, 176 SD_D1, 177 SD_D0, 178 SD_CLK, 179 SD_CMD, 180 SD_D3, 181 SD_D2, 182 VCC_3V0, 183 HDMI_HPD, 184 HDMI_SCL, 185 HDMI_SDA, 186 HDMI_CEC, 187 HDMI_TXCN, 188 HDMI_TXCP, 189 HDMI_TX0N, 190 HDMI_RXOP

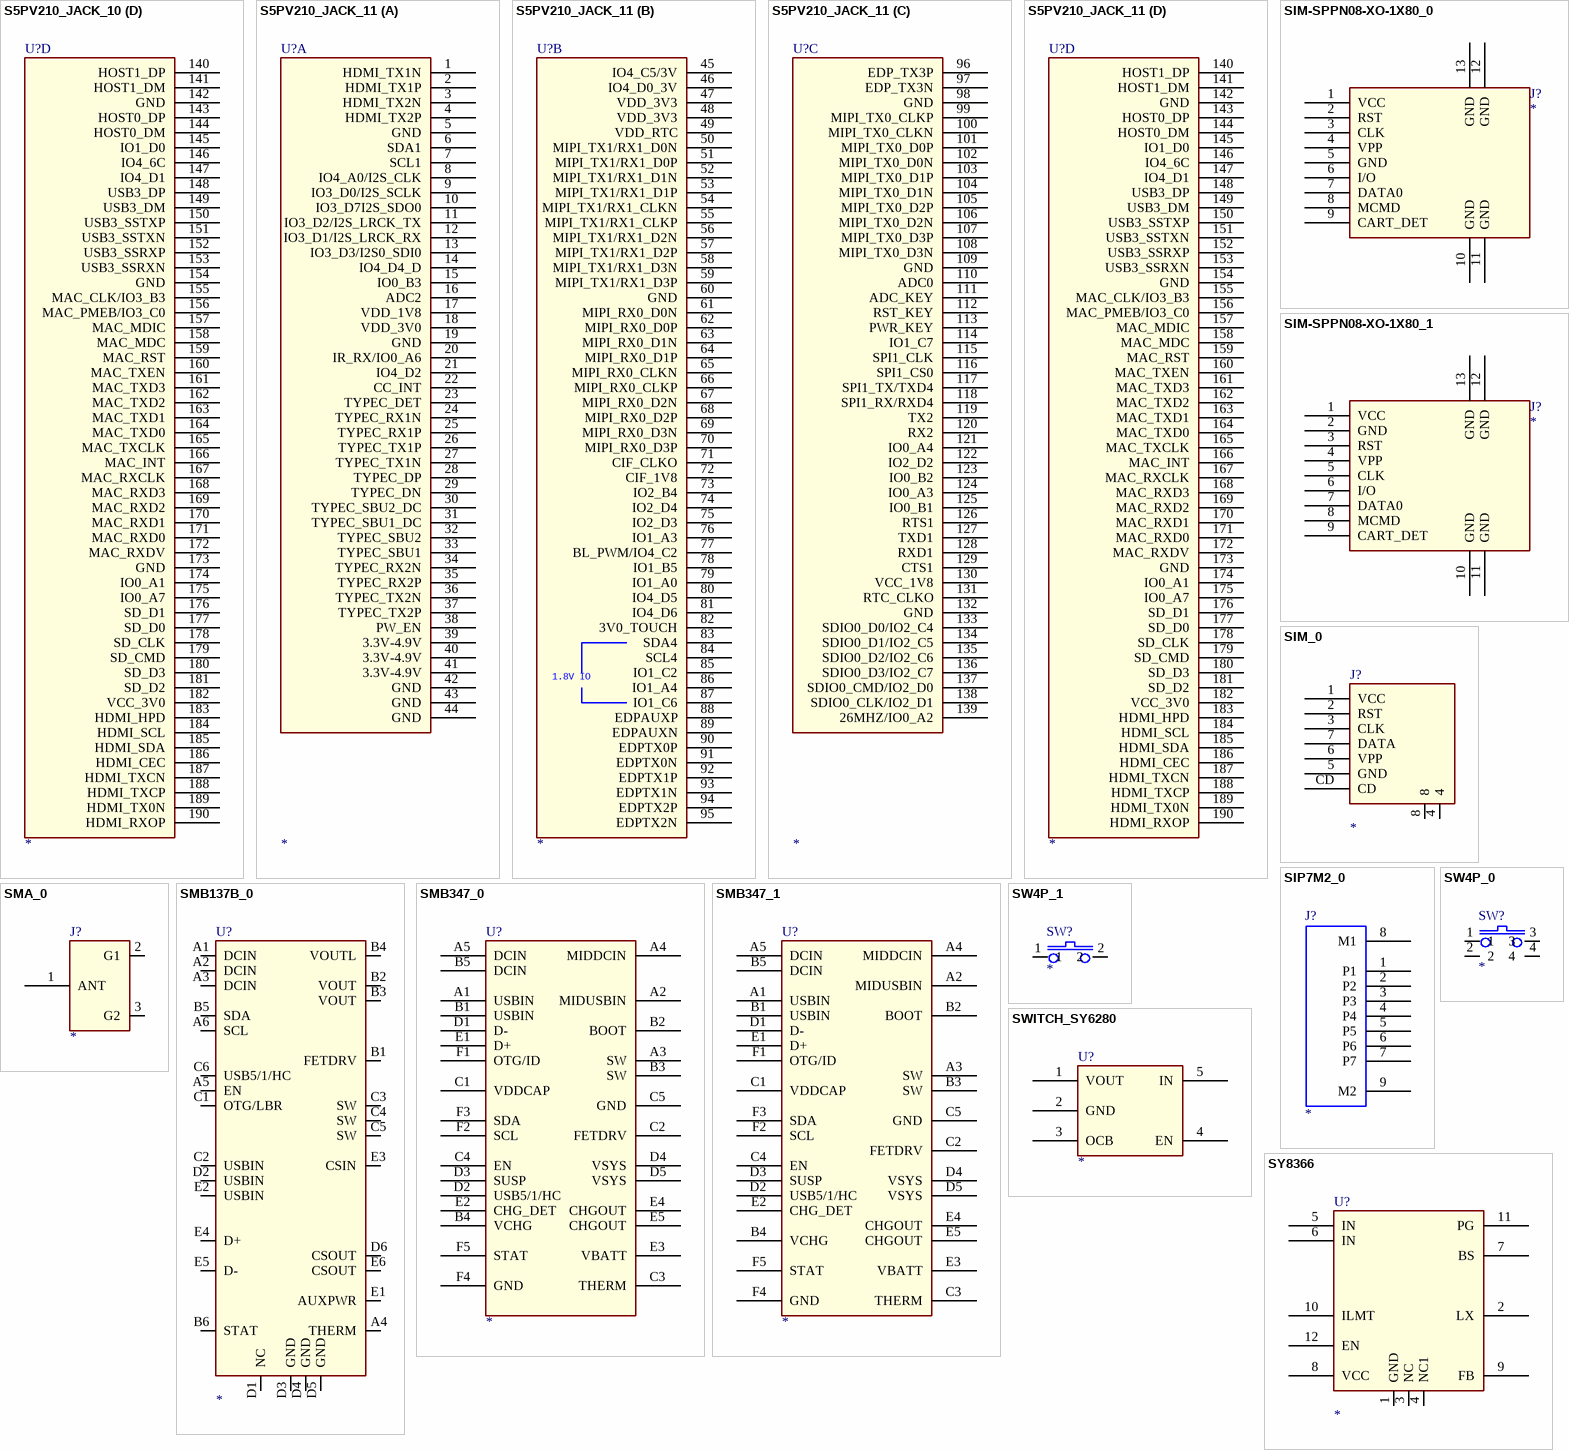
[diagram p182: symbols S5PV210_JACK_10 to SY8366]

## S5PV210_JACK_10
designator U?
footprint S5PV210_JACK
part A pins: 1 HDMI_TX1N, 2 HDMI_TX1P, 3 HDMI_TX2N, 4 HDMI_TX2P, 5 GND (power), 6 SDA1, 7 SCL1, 8 IO4_A0/I2S_CLK, 9 IO3_D0/I2S_SCLK, 10 IO3_D7I2S_SDO0, 11 IO3_D2/I2S_LRCK_TX, 12 IO3_D1/I2S_LRCK_RX, 13 IO3_D3/I2S0_SDI0, 14 IO4_D4_D, 15 IO0_B3, 16 ADC2, 17 VDD_1V8, 18 VDD_3V0, 19 GND (power), 20 IR_RX/IO0_A6, 21 IO4_D2, 22 CC_INT, 23 TYPEC_DET, 24 TYPEC_RX1N, 25 TYPEC_RX1P, 26 TYPEC_TX1P, 27 TYPEC_TX1N, 28 TYPEC_DP, 29 TYPEC_DN, 30 TYPEC_SBU2_DC, 31 TYPEC_SBU1_DC, 32 TYPEC_SBU2, 33 TYPEC_SBU1, 34 TYPEC_RX2N, 35 TYPEC_RX2P, 36 TYPEC_TX2N, 37 TYPEC_TX2P, 38 PW_EN, 39 3.3V-4.9V (power), 40 3.3V-4.9V (power), 41 3.3V-4.9V (power), 42 GND (power), 43 GND (power), 44 GND (power)
part B pins: 45 IO4_C5/3V, 46 IO4_D0_3V, 47 VDD_3V3 (power), 48 VDD_3V3 (power), 49 VDD_RTC, 50 MIPI_TX1/RX1_D0N, 51 MIPI_TX1/RX1_D0P, 52 MIPI_TX1/RX1_D1N, 53 MIPI_TX1/RX1_D1P, 54 MIPI_TX1/RX1_CLKN, 55 MIPI_TX1/RX1_CLKP, 56 MIPI_TX1/RX1_D2N, 57 MIPI_TX1/RX1_D2P, 58 MIPI_TX1/RX1_D3N, 59 MIPI_TX1/RX1_D3P, 60 GND, 61 MIPI_RX0_D0N, 62 MIPI_RX0_D0P, 63 MIPI_RX0_D1N, 64 MIPI_RX0_D1P, 65 MIPI_RX0_CLKN, 66 MIPI_RX0_CLKP, 67 MIPI_RX0_D2N, 68 MIPI_RX0_D2P, 69 MIPI_RX0_D3N, 70 MIPI_RX0_D3P, 71 CIF_CLKO, 72 CIF_1V8, 73 IO2_B4, 74 IO2_D4, 75 IO2_D3, 76 IO1_A3, 77 BL_PWM/IO4_C2, 78 IO1_B5, 79 IO1_A0, 80 IO4_D5, 81 IO4_D6, 82 3V0_TOUCH, 83 SDA4, 84 SCL4, 85 IO1_C2, 86 IO1_A4, 87 IO1_C6, 88 EDPAUXP, 89 EDPAUXN, 90 EDPTX0P, 91 EDPTX0N, 92 EDPTX1P, 93 EDPTX1N, 94 EDPTX2P, 95 EDPTX2N
part C pins: 96 EDP_TX3P, 97 EDP_TX3N, 98 GND (power), 99 MIPI_TX0_CLKP, 100 MIPI_TX0_CLKN, 101 MIPI_TX0_D0P, 102 MIPI_TX0_D0N, 103 MIPI_TX0_D1P, 104 MIPI_TX0_D1N, 105 MIPI_TX0_D2P, 106 MIPI_TX0_D2N, 107 MIPI_TX0_D3P, 108 MIPI_TX0_D3N, 109 GND (power), 110 ADC0, 111 ADC_KEY, 112 RST_KEY, 113 PWR_KEY, 114 IO1_C7, 115 SPI1_CLK, 116 SPI1_CS0, 117 SPI1_TX/TXD4, 118 SPI1_RX/RXD4, 119 TX2, 120 RX2, 121 IO0_A4, 122 IO2_D2, 123 IO0_B2, 124 IO0_A3, 125 IO0_B1, 126 RTS1, 127 TXD1, 128 RXD1, 129 CTS1, 130 VCC_1V8, 131 RTC_CLKO, 132 GND (power), 133 SDIO0_D0/IO2_C4, 134 SDIO0_D1/IO2_C5, 135 SDIO0_D2/IO2_C6, 136 SDIO0_D3/IO2_C7, 137 SDIO0_CMD/IO2_D0, 138 SDIO0_CLK/IO2_D1, 139 26MHZ/IO0_A2
part D pins: 140 HOST1_DP, 141 HOST1_DM, 142 GND (power), 143 HOST0_DP, 144 HOST0_DM, 145 IO1_D0, 146 IO4_6C, 147 IO4_D1, 148 USB3_DP, 149 USB3_DM, 150 USB3_SSTXP, 151 USB3_SSTXN, 152 USB3_SSRXP, 153 USB3_SSRXN, 154 GND (power), 155 MAC_CLK/IO3_B3, 156 MAC_PMEB/IO3_C0, 157 MAC_MDIC, 158 MAC_MDC, 159 MAC_RST, 160 MAC_TXEN, 161 MAC_TXD3, 162 MAC_TXD2, 163 MAC_TXD1, 164 MAC_TXD0, 165 MAC_TXCLK, 166 MAC_INT, 167 MAC_RXCLK, 168 MAC_RXD3, 169 MAC_RXD2, 170 MAC_RXD1, 171 MAC_RXD0, 172 MAC_RXDV, 173 GND (power), 174 IO0_A1, 175 IO0_A7, 176 SD_D1, 177 SD_D0, 178 SD_CLK, 179 SD_CMD, 180 SD_D3, 181 SD_D2, 182 VCC_3V0, 183 HDMI_HPD, 184 HDMI_SCL, 185 HDMI_SDA, 186 HDMI_CEC, 187 HDMI_TXCN, 188 HDMI_TXCP, 189 HDMI_TX0N, 190 HDMI_RXOP

## S5PV210_JACK_11
designator U?
footprint S5PV210_JACK
part A pins: 1 HDMI_TX1N, 2 HDMI_TX1P, 3 HDMI_TX2N, 4 HDMI_TX2P, 5 GND (power), 6 SDA1, 7 SCL1, 8 IO4_A0/I2S_CLK, 9 IO3_D0/I2S_SCLK, 10 IO3_D7I2S_SDO0, 11 IO3_D2/I2S_LRCK_TX, 12 IO3_D1/I2S_LRCK_RX, 13 IO3_D3/I2S0_SDI0, 14 IO4_D4_D, 15 IO0_B3, 16 ADC2, 17 VDD_1V8, 18 VDD_3V0, 19 GND (power), 20 IR_RX/IO0_A6, 21 IO4_D2, 22 CC_INT, 23 TYPEC_DET, 24 TYPEC_RX1N, 25 TYPEC_RX1P, 26 TYPEC_TX1P, 27 TYPEC_TX1N, 28 TYPEC_DP, 29 TYPEC_DN, 30 TYPEC_SBU2_DC, 31 TYPEC_SBU1_DC, 32 TYPEC_SBU2, 33 TYPEC_SBU1, 34 TYPEC_RX2N, 35 TYPEC_RX2P, 36 TYPEC_TX2N, 37 TYPEC_TX2P, 38 PW_EN, 39 3.3V-4.9V (power), 40 3.3V-4.9V (power), 41 3.3V-4.9V (power), 42 GND (power), 43 GND (power), 44 GND (power)
part B pins: 45 IO4_C5/3V, 46 IO4_D0_3V, 47 VDD_3V3 (power), 48 VDD_3V3 (power), 49 VDD_RTC, 50 MIPI_TX1/RX1_D0N, 51 MIPI_TX1/RX1_D0P, 52 MIPI_TX1/RX1_D1N, 53 MIPI_TX1/RX1_D1P, 54 MIPI_TX1/RX1_CLKN, 55 MIPI_TX1/RX1_CLKP, 56 MIPI_TX1/RX1_D2N, 57 MIPI_TX1/RX1_D2P, 58 MIPI_TX1/RX1_D3N, 59 MIPI_TX1/RX1_D3P, 60 GND, 61 MIPI_RX0_D0N, 62 MIPI_RX0_D0P, 63 MIPI_RX0_D1N, 64 MIPI_RX0_D1P, 65 MIPI_RX0_CLKN, 66 MIPI_RX0_CLKP, 67 MIPI_RX0_D2N, 68 MIPI_RX0_D2P, 69 MIPI_RX0_D3N, 70 MIPI_RX0_D3P, 71 CIF_CLKO, 72 CIF_1V8, 73 IO2_B4, 74 IO2_D4, 75 IO2_D3, 76 IO1_A3, 77 BL_PWM/IO4_C2, 78 IO1_B5, 79 IO1_A0, 80 IO4_D5, 81 IO4_D6, 82 3V0_TOUCH, 83 SDA4, 84 SCL4, 85 IO1_C2, 86 IO1_A4, 87 IO1_C6, 88 EDPAUXP, 89 EDPAUXN, 90 EDPTX0P, 91 EDPTX0N, 92 EDPTX1P, 93 EDPTX1N, 94 EDPTX2P, 95 EDPTX2N
part C pins: 96 EDP_TX3P, 97 EDP_TX3N, 98 GND (power), 99 MIPI_TX0_CLKP, 100 MIPI_TX0_CLKN, 101 MIPI_TX0_D0P, 102 MIPI_TX0_D0N, 103 MIPI_TX0_D1P, 104 MIPI_TX0_D1N, 105 MIPI_TX0_D2P, 106 MIPI_TX0_D2N, 107 MIPI_TX0_D3P, 108 MIPI_TX0_D3N, 109 GND (power), 110 ADC0, 111 ADC_KEY, 112 RST_KEY, 113 PWR_KEY, 114 IO1_C7, 115 SPI1_CLK, 116 SPI1_CS0, 117 SPI1_TX/TXD4, 118 SPI1_RX/RXD4, 119 TX2, 120 RX2, 121 IO0_A4, 122 IO2_D2, 123 IO0_B2, 124 IO0_A3, 125 IO0_B1, 126 RTS1, 127 TXD1, 128 RXD1, 129 CTS1, 130 VCC_1V8, 131 RTC_CLKO, 132 GND (power), 133 SDIO0_D0/IO2_C4, 134 SDIO0_D1/IO2_C5, 135 SDIO0_D2/IO2_C6, 136 SDIO0_D3/IO2_C7, 137 SDIO0_CMD/IO2_D0, 138 SDIO0_CLK/IO2_D1, 139 26MHZ/IO0_A2
part D pins: 140 HOST1_DP, 141 HOST1_DM, 142 GND (power), 143 HOST0_DP, 144 HOST0_DM, 145 IO1_D0, 146 IO4_6C, 147 IO4_D1, 148 USB3_DP, 149 USB3_DM, 150 USB3_SSTXP, 151 USB3_SSTXN, 152 USB3_SSRXP, 153 USB3_SSRXN, 154 GND (power), 155 MAC_CLK/IO3_B3, 156 MAC_PMEB/IO3_C0, 157 MAC_MDIC, 158 MAC_MDC, 159 MAC_RST, 160 MAC_TXEN, 161 MAC_TXD3, 162 MAC_TXD2, 163 MAC_TXD1, 164 MAC_TXD0, 165 MAC_TXCLK, 166 MAC_INT, 167 MAC_RXCLK, 168 MAC_RXD3, 169 MAC_RXD2, 170 MAC_RXD1, 171 MAC_RXD0, 172 MAC_RXDV, 173 GND (power), 174 IO0_A1, 175 IO0_A7, 176 SD_D1, 177 SD_D0, 178 SD_CLK, 179 SD_CMD, 180 SD_D3, 181 SD_D2, 182 VCC_3V0, 183 HDMI_HPD, 184 HDMI_SCL, 185 HDMI_SDA, 186 HDMI_CEC, 187 HDMI_TXCN, 188 HDMI_TXCP, 189 HDMI_TX0N, 190 HDMI_RXOP

## SIM-SPPN08-XO-1X80_0
designator J?
footprint SIM-SPPN08-XO-1X80
pins: 1 VCC, 2 RST, 3 CLK, 4 VPP, 5 GND, 6 I/O, 7 DATA0, 8 MCMD, 9 CART_DET, 10 GND, 11 GND, 12 GND, 13 GND

## SIM-SPPN08-XO-1X80_1
designator J?
footprint SIM-SPPN08-XO-1X80
pins: 1 VCC, 2 GND, 3 RST, 4 VPP, 5 CLK, 6 I/O, 7 DATA0, 8 MCMD, 9 CART_DET, 10 GND, 11 GND, 12 GND, 13 GND

## SIM_0
designator J?
footprint SIM_1
pins: 1 VCC, 2 RST, 3 CLK, 4, 5 GND, 6 VPP, 7 DATA, 8, CD

## SIP7M2_0
designator J?
PARTS: 1; OriginalSymbolOrigin: (10,130); CODE: 184999; PKG_TYPE: 9; LEVEL: STD; DEVICE: 67491-1032
pins: 1 P1, 2 P2, 3 P3, 4 P4, 5 P5, 6 P6, 7 P7, 8 M1, 9 M2

## SMA_0
designator J?
footprint ANT5_SMA_ST_EM1
pins: 1 ANT, 2 G1, 3 G2

## SMB137B_0
designator U?
pins: A1 DCIN, A2 DCIN, A3 DCIN, A4 THERM, A5 EN, A6 SCL, B1 FETDRV, B2 VOUT, B3 VOUT, B4 VOUTL, B5 SDA, B6 STAT, C1 OTG/LBR, C2 USBIN, C3 SW, C4 SW, C5 SW, C6 USB5/1/HC, D1 NC, D2 USBIN, D3 GND, D4 GND, D5 GND, D6 CSOUT, E1 AUXPWR, E2 USBIN, E3 CSIN, E4 D+, E5 D-, E6 CSOUT

## SMB347_0
designator U?
footprint BGA30-3X2.5
pins: A1 USBIN, A2 MIDUSBIN, A3 SW, A4 MIDDCIN, A5 DCIN, B1 USBIN, B2 BOOT, B3 SW, B4 VCHG, B5 DCIN, C1 VDDCAP, C2 FETDRV, C3 THERM, C4 EN, C5 GND, D1 D-, D2 USB5/1/HC, D3 SUSP, D4 VSYS, D5 VSYS, E1 D+, E2 CHG_DET, E3 VBATT, E4 CHGOUT, E5 CHGOUT, F1 OTG/ID, F2 SCL, F3 SDA, F4 GND, F5 STAT

## SMB347_1
designator U?
footprint BGA30-3X2.5
pins: A1 USBIN, A2 MIDUSBIN, A3 SW, A4 MIDDCIN, A5 DCIN, B1 USBIN, B2 BOOT, B3 SW, B4 VCHG, B5 DCIN, C1 VDDCAP, C2 FETDRV, C3 THERM, C4 EN, C5 GND, D1 D-, D2 USB5/1/HC, D3 SUSP, D4 VSYS, D5 VSYS, E1 D+, E2 CHG_DET, E3 VBATT, E4 CHGOUT, E5 CHGOUT, F1 OTG/ID, F2 SCL, F3 SDA, F4 GND, F5 STAT

## SW4P_0
designator SW?
pins: 1, 2, 3, 4

## SW4P_1
designator SW?
pins: 1, 2

## SWITCH_SY6280
designator U?
pins: 1 VOUT, 2 GND, 3 OCB, 4 EN, 5 IN

## SY8366
designator U?
pins: 1 GND, 2 LX, 3 NC (power), 4 NC1 (power), 5 IN (power), 6 IN (power), 7 BS, 8 VCC, 9 FB, 10 ILMT, 11 PG, 12 EN

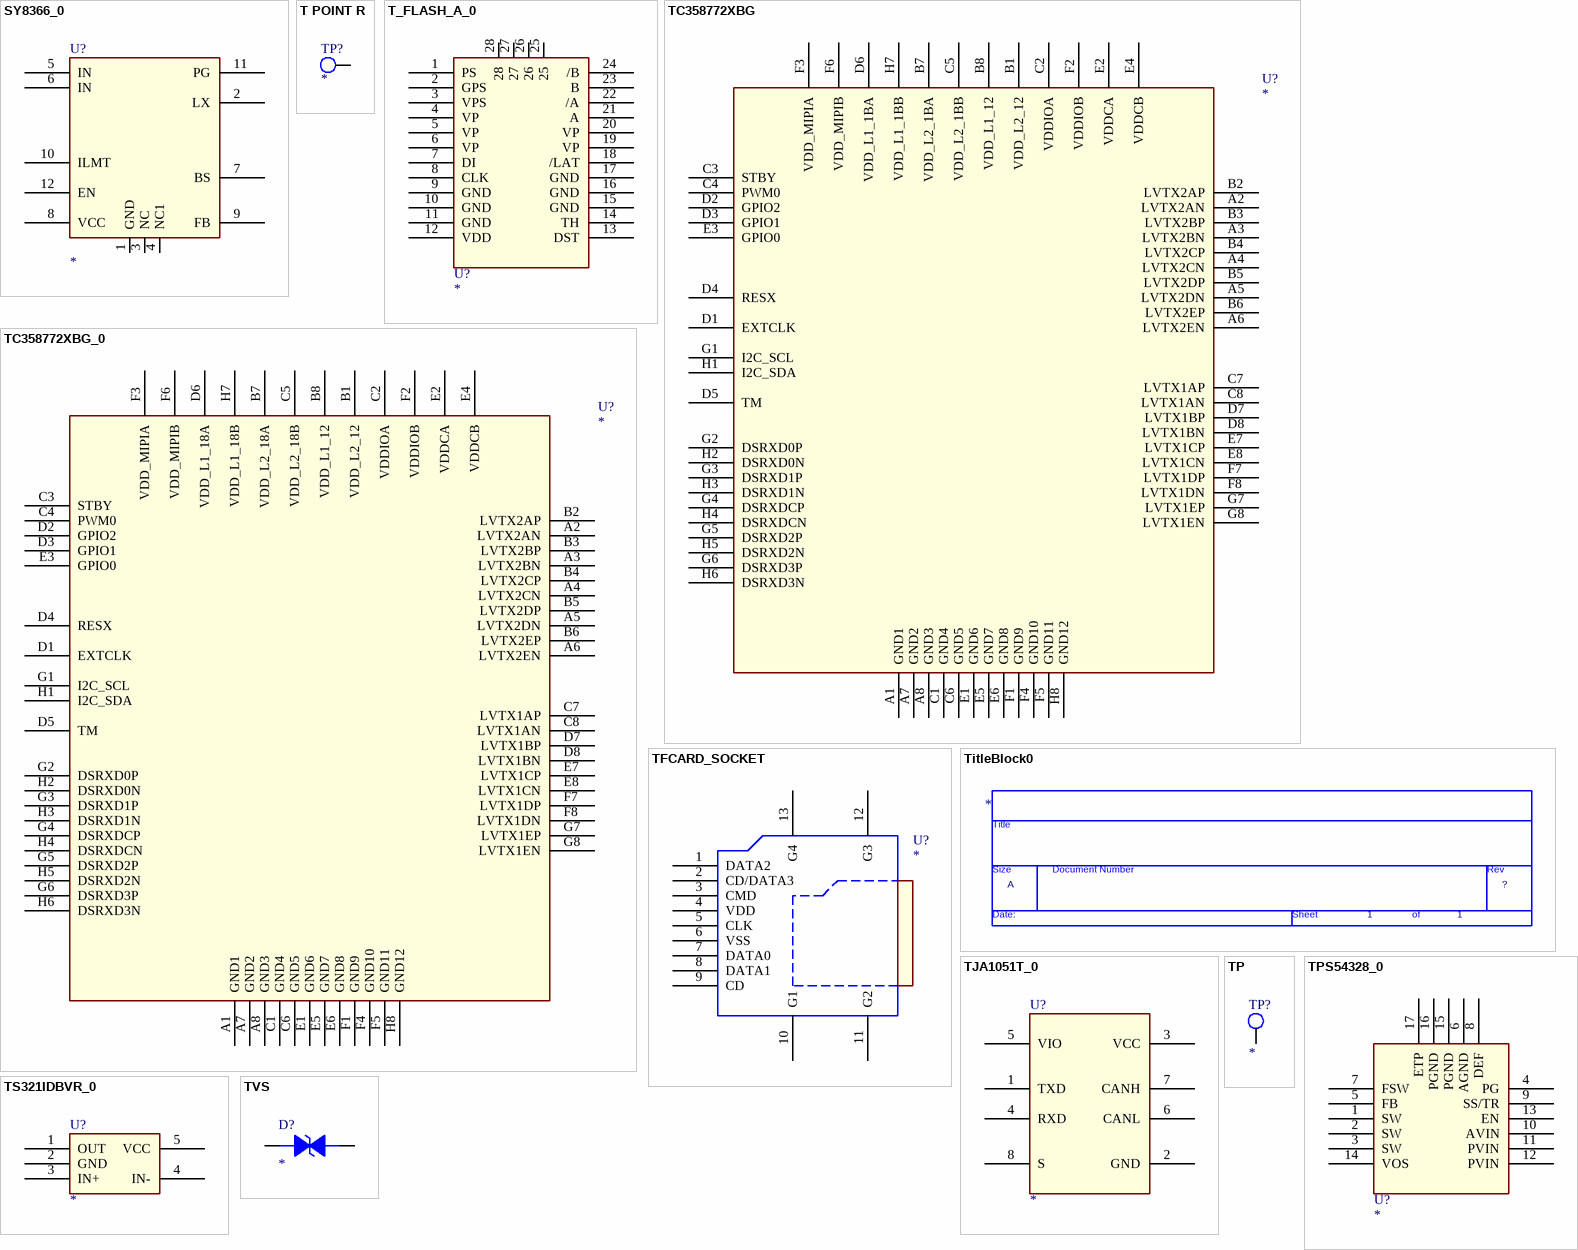
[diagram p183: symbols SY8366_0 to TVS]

## SY8366_0
designator U?
pins: 1 GND, 2 LX, 3 NC (power), 4 NC1 (power), 5 IN (power), 6 IN (power), 7 BS, 8 VCC, 9 FB, 10 ILMT, 11 PG, 12 EN

## T POINT R
designator TP?
pins: 1 TP

## T_FLASH_A_0
designator U?
footprint TFLASH-MOLEX-WITHSWITCH
pins: 1 PS, 2 GPS, 3 VPS, 4 VP, 5 VP, 6 VP, 7 DI, 8 CLK, 9 GND, 10 GND, 11 GND, 12 VDD, 13 DST, 14 TH, 15 GND, 16 GND, 17 GND, 18 /LAT, 19 VP, 20 VP, 21 A, 22 /A, 23 B, 24 /B, 25, 26, 27, 28

## TC358772XBG
designator U?
pins: A1 GND1, A2 LVTX2AN, A3 LVTX2BN, A4 LVTX2CN, A5 LVTX2DN, A6 LVTX2EN, A7 GND2, A8 GND3, B1 VDD_L2_12, B2 LVTX2AP, B3 LVTX2BP, B4 LVTX2CP, B5 LVTX2DP, B6 LVTX2EP, B7 VDD_L2_1BA, B8 VDD_L1_12, C1 GND4, C2 VDDIOA, C3 STBY, C4 PWM0, C5 VDD_L2_1BB, C6 GND5, C7 LVTX1AP, C8 LVTX1AN, D1 EXTCLK, D2 GPIO2, D3 GPIO1, D4 RESX, D5 TM, D6 VDD_L1_1BA, D7 LVTX1BP, D8 LVTX1BN, E1 GND6, E2 VDDCA, E3 GPIO0, E4 VDDCB, E5 GND7, E6 GND8, E7 LVTX1CP, E8 LVTX1CN, F1 GND9, F2 VDDIOB, F3 VDD_MIPIA, F4 GND10, F5 GND11, F6 VDD_MIPIB, F7 LVTX1DP, F8 LVTX1DN, G1 I2C_SCL, G2 DSRXD0P, G3 DSRXD1P, G4 DSRXDCP, G5 DSRXD2P, G6 DSRXD3P, G7 LVTX1EP, G8 LVTX1EN, H1 I2C_SDA, H2 DSRXD0N, H3 DSRXD1N, H4 DSRXDCN, H5 DSRXD2N, H6 DSRXD3N, H7 VDD_L1_1BB, H8 GND12

## TC358772XBG_0
designator U?
pins: A1 GND1, A2 LVTX2AN, A3 LVTX2BN, A4 LVTX2CN, A5 LVTX2DN, A6 LVTX2EN, A7 GND2, A8 GND3, B1 VDD_L2_12, B2 LVTX2AP, B3 LVTX2BP, B4 LVTX2CP, B5 LVTX2DP, B6 LVTX2EP, B7 VDD_L2_18A, B8 VDD_L1_12, C1 GND4, C2 VDDIOA, C3 STBY, C4 PWM0, C5 VDD_L2_18B, C6 GND5, C7 LVTX1AP, C8 LVTX1AN, D1 EXTCLK, D2 GPIO2, D3 GPIO1, D4 RESX, D5 TM, D6 VDD_L1_18A, D7 LVTX1BP, D8 LVTX1BN, E1 GND6, E2 VDDCA, E3 GPIO0, E4 VDDCB, E5 GND7, E6 GND8, E7 LVTX1CP, E8 LVTX1CN, F1 GND9, F2 VDDIOB, F3 VDD_MIPIA, F4 GND10, F5 GND11, F6 VDD_MIPIB, F7 LVTX1DP, F8 LVTX1DN, G1 I2C_SCL, G2 DSRXD0P, G3 DSRXD1P, G4 DSRXDCP, G5 DSRXD2P, G6 DSRXD3P, G7 LVTX1EP, G8 LVTX1EN, H1 I2C_SDA, H2 DSRXD0N, H3 DSRXD1N, H4 DSRXDCN, H5 DSRXD2N, H6 DSRXD3N, H7 VDD_L1_18B, H8 GND12

## TFCARD_SOCKET
designator U?
footprint TF-CKT01-009D
pins: 1 DATA2, 2 CD/DATA3, 3 CMD, 4 VDD, 5 CLK, 6 VSS, 7 DATA0, 8 DATA1, 9 CD, 10 G1, 11 G2, 12 G3, 13 G4

## TitleBlock0
designator *  Page Size: A  Page Number: 1  (graphical)

## TJA1051T_0
designator U?
pins: 1 TXD, 2 GND, 3 VCC, 4 RXD, 5 VIO, 6 CANL, 7 CANH, 8 S

## TP
designator TP?
footprint TEST
pins: 1

## TPS54328_0
designator U?
footprint SOP8A
pins: 1 SW, 2 SW, 3 SW, 4 PG, 5 FB, 6 AGND, 7 FSW, 8 DEF, 9 SS/TR, 10 AVIN, 11 PVIN, 12 PVIN, 13 EN, 14 VOS, 15 PGND, 16 PGND, 17 ETP

## TS321IDBVR_0
designator U?
footprint SOT25
pins: 1 OUT, 2 GND, 3 IN+, 4 IN-, 5 VCC

## TVS
designator D?
footprint E0402N
pins: 1, 2

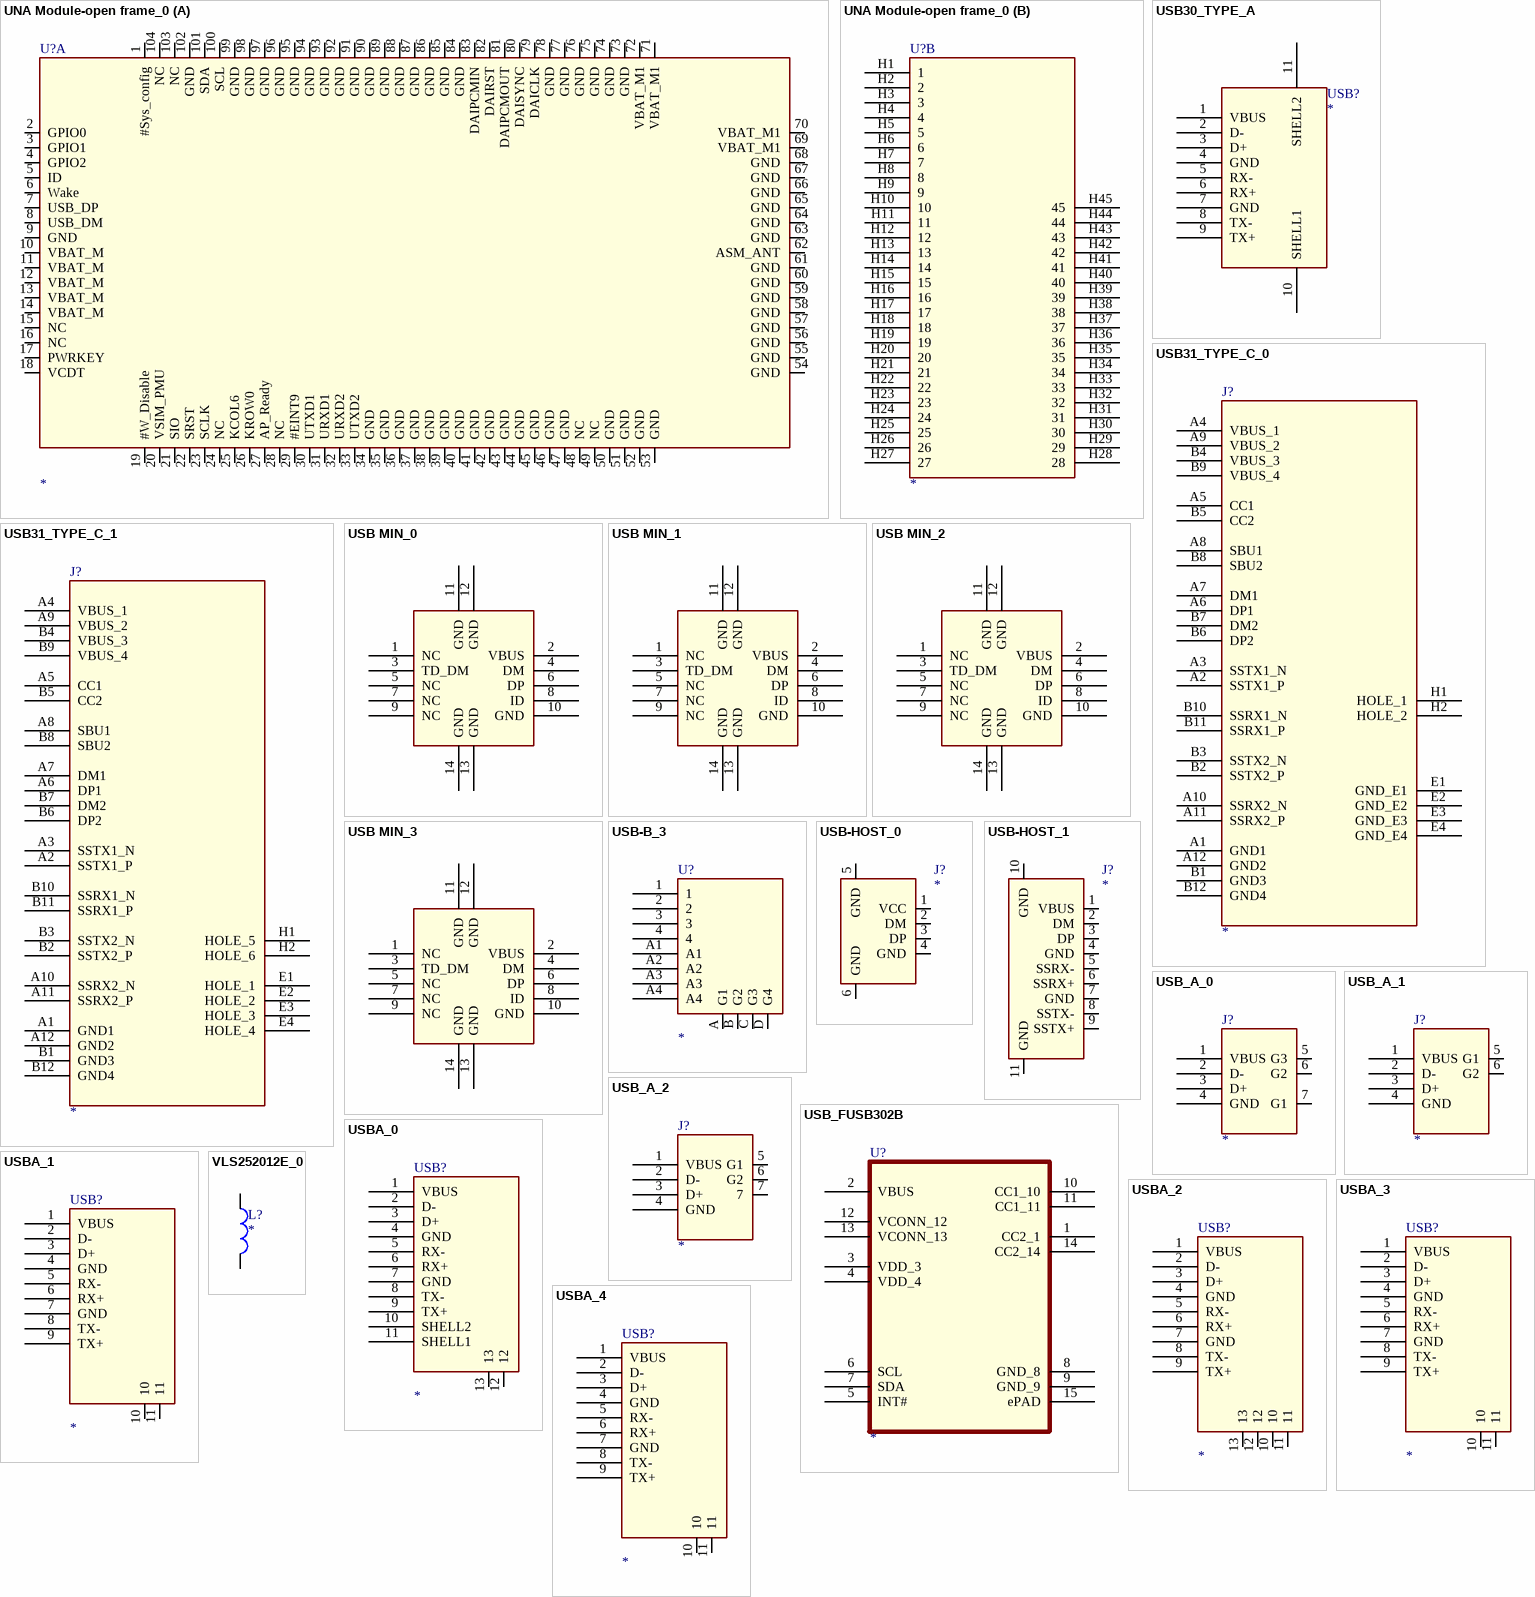
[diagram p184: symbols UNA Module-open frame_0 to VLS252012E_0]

## UNA Module-open frame_0
designator U?
part A pins: 1 #Sys_config, 2 GPIO0, 3 GPIO1, 4 GPIO2, 5 ID, 6 Wake, 7 USB_DP, 8 USB_DM, 9 GND, 10 VBAT_M, 11 VBAT_M, 12 VBAT_M, 13 VBAT_M, 14 VBAT_M, 15 NC, 16 NC, 17 PWRKEY, 18 VCDT, 19 #W_Disable, 20 VSIM_PMU, 21 SIO, 22 SRST, 23 SCLK, 24 NC, 25 KCOL6, 26 KROW0, 27 AP_Ready, 28 NC, 29 #EINT9, 30 UTXD1, 31 URXD1, 32 URXD2, 33 UTXD2, 34 GND, 35 GND, 36 GND, 37 GND, 38 GND, 39 GND, 40 GND, 41 GND, 42 GND, 43 GND, 44 GND, 45 GND, 46 GND, 47 GND, 48 NC, 49 NC, 50 GND, 51 GND, 52 GND, 53 GND, 54 GND, 55 GND, 56 GND, 57 GND, 58 GND, 59 GND, 60 GND, 61 GND, 62 ASM_ANT, 63 GND, 64 GND, 65 GND, 66 GND, 67 GND, 68 GND, 69 VBAT_M1, 70 VBAT_M1, 71 VBAT_M1, 72 VBAT_M1, 73 GND, 74 GND, 75 GND, 76 GND, 77 GND, 78 GND, 79 DAICLK, 80 DAISYNC, 81 DAIPCMOUT, 82 DAIRST, 83 DAIPCMIN, 84 GND, 85 GND, 86 GND, 87 GND, 88 GND, 89 GND, 90 GND, 91 GND, 92 GND, 93 GND, 94 GND, 95 GND, 96 GND, 97 GND, 98 GND, 99 GND, 100 SCL, 101 SDA, 102 GND, 103 NC, 104 NC
part B pins: H1 1, H2 2, H3 3, H4 4, H5 5, H6 6, H7 7, H8 8, H9 9, H10 10, H11 11, H12 12, H13 13, H14 14, H15 15, H16 16, H17 17, H18 18, H19 19, H20 20, H21 21, H22 22, H23 23, H24 24, H25 25, H26 26, H27 27, H28 28, H29 29, H30 30, H31 31, H32 32, H33 33, H34 34, H35 35, H36 36, H37 37, H38 38, H39 39, H40 40, H41 41, H42 42, H43 43, H44 44, H45 45

## USB30_TYPE_A
designator USB?
footprint USB30
pins: 1 VBUS (power), 2 D-, 3 D+, 4 GND (power), 5 RX-, 6 RX+, 7 GND (power), 8 TX-, 9 TX+, 10 SHELL1, 11 SHELL2

## USB31_TYPE_C_0
designator J?
pins: A1 GND1, A2 SSTX1_P, A3 SSTX1_N, A4 VBUS_1, A5 CC1, A6 DP1, A7 DM1, A8 SBU1, A9 VBUS_2, A10 SSRX2_N, A11 SSRX2_P, A12 GND2, B1 GND3, B2 SSTX2_P, B3 SSTX2_N, B4 VBUS_3, B5 CC2, B6 DP2, B7 DM2, B8 SBU2, B9 VBUS_4, B10 SSRX1_N, B11 SSRX1_P, B12 GND4, E1 GND_E1, E2 GND_E2, E3 GND_E3, E4 GND_E4, H1 HOLE_1, H2 HOLE_2

## USB31_TYPE_C_1
designator J?
pins: A1 GND1, A2 SSTX1_P, A3 SSTX1_N, A4 VBUS_1, A5 CC1, A6 DP1, A7 DM1, A8 SBU1, A9 VBUS_2, A10 SSRX2_N, A11 SSRX2_P, A12 GND2, B1 GND3, B2 SSTX2_P, B3 SSTX2_N, B4 VBUS_3, B5 CC2, B6 DP2, B7 DM2, B8 SBU2, B9 VBUS_4, B10 SSRX1_N, B11 SSRX1_P, B12 GND4, E1 HOLE_1, E2 HOLE_2, E3 HOLE_3, E4 HOLE_4, H1 HOLE_5, H2 HOLE_6

## USB MIN_0
designator J?
pins: 1 NC, 2 VBUS, 3 TD_DM, 4 DM, 5 NC (power), 6 DP, 7 NC, 8 ID, 9 NC, 10 GND, 11 GND, 12 GND, 13 GND, 14 GND

## USB MIN_1
designator J?
pins: 1 NC, 2 VBUS, 3 TD_DM, 4 DM, 5 NC (power), 6 DP, 7 NC, 8 ID, 9 NC, 10 GND, 11 GND, 12 GND, 13 GND, 14 GND

## USB MIN_2
designator J?
pins: 1 NC, 2 VBUS, 3 TD_DM, 4 DM, 5 NC, 6 DP, 7 NC, 8 ID, 9 NC, 10 GND, 11 GND, 12 GND, 13 GND, 14 GND

## USB MIN_3
designator J?
pins: 1 NC, 2 VBUS, 3 TD_DM, 4 DM, 5 NC, 6 DP, 7 NC, 8 ID, 9 NC, 10 GND, 11 GND, 12 GND, 13 GND, 14 GND

## USB-B_3
designator U?
pins: 1, 2, 3, 4, A G1 (power), A1, A2, A3, A4, B G2 (power), C G3 (power), D G4 (power)

## USB-HOST_0
designator J?
footprint USB-HOST
pins: 1 VCC, 2 DM, 3 DP, 4 GND, 5 GND, 6 GND

## USB-HOST_1
designator J?
footprint USB-HOST
pins: 1 VBUS, 2 DM, 3 DP, 4 GND, 5 SSRX-, 6 SSRX+, 7 GND, 8 SSTX-, 9 SSTX+, 10 GND, 11 GND

## USB_A_0
designator J?
pins: 1 VBUS, 2 D-, 3 D+, 4 GND, 5 G3 (power), 6 G2 (power), 7 G1 (power)

## USB_A_1
designator J?
pins: 1 VBUS, 2 D-, 3 D+, 4 GND, 5 G1, 6 G2

## USB_A_2
designator J?
pins: 1 VBUS, 2 D-, 3 D+, 4 GND, 5 G1, 6 G2, 7

## USB_FUSB302B
designator U?
footprint MLP14_2R50X2R50X0R80
pins: 1 CC2_1, 2 VBUS, 3 VDD_3 (power), 4 VDD_4 (power), 5 INT#, 6 SCL, 7 SDA, 8 GND_8 (power), 9 GND_9 (power), 10 CC1_10, 11 CC1_11, 12 VCONN_12, 13 VCONN_13, 14 CC2_14, 15 ePAD (power)

## USBA_0
designator USB?
footprint USB30
pins: 1 VBUS (power), 2 D-, 3 D+, 4 GND (power), 5 RX-, 6 RX+, 7 GND (power), 8 TX-, 9 TX+, 10 SHELL2, 11 SHELL1, 12 (power), 13 (power)

## USBA_1
designator USB?
footprint USB30
pins: 1 VBUS (power), 2 D-, 3 D+, 4 GND (power), 5 RX-, 6 RX+, 7 GND (power), 8 TX-, 9 TX+, 10 (power), 11 (power)

## USBA_2
designator USB?
footprint USB30
pins: 1 VBUS (power), 2 D-, 3 D+, 4 GND (power), 5 RX-, 6 RX+, 7 GND (power), 8 TX-, 9 TX+, 10 (power), 11 (power), 12, 13

## USBA_3
designator USB?
footprint USB30
pins: 1 VBUS (power), 2 D-, 3 D+, 4 GND (power), 5 RX-, 6 RX+, 7 GND (power), 8 TX-, 9 TX+, 10, 11

## USBA_4
designator USB?
footprint USB30
pins: 1 VBUS (power), 2 D-, 3 D+, 4 GND (power), 5 RX-, 6 RX+, 7 GND (power), 8 TX-, 9 TX+, 10, 11

## VLS252012E_0
designator L?
footprint VLS252012E
pins: 1, 2

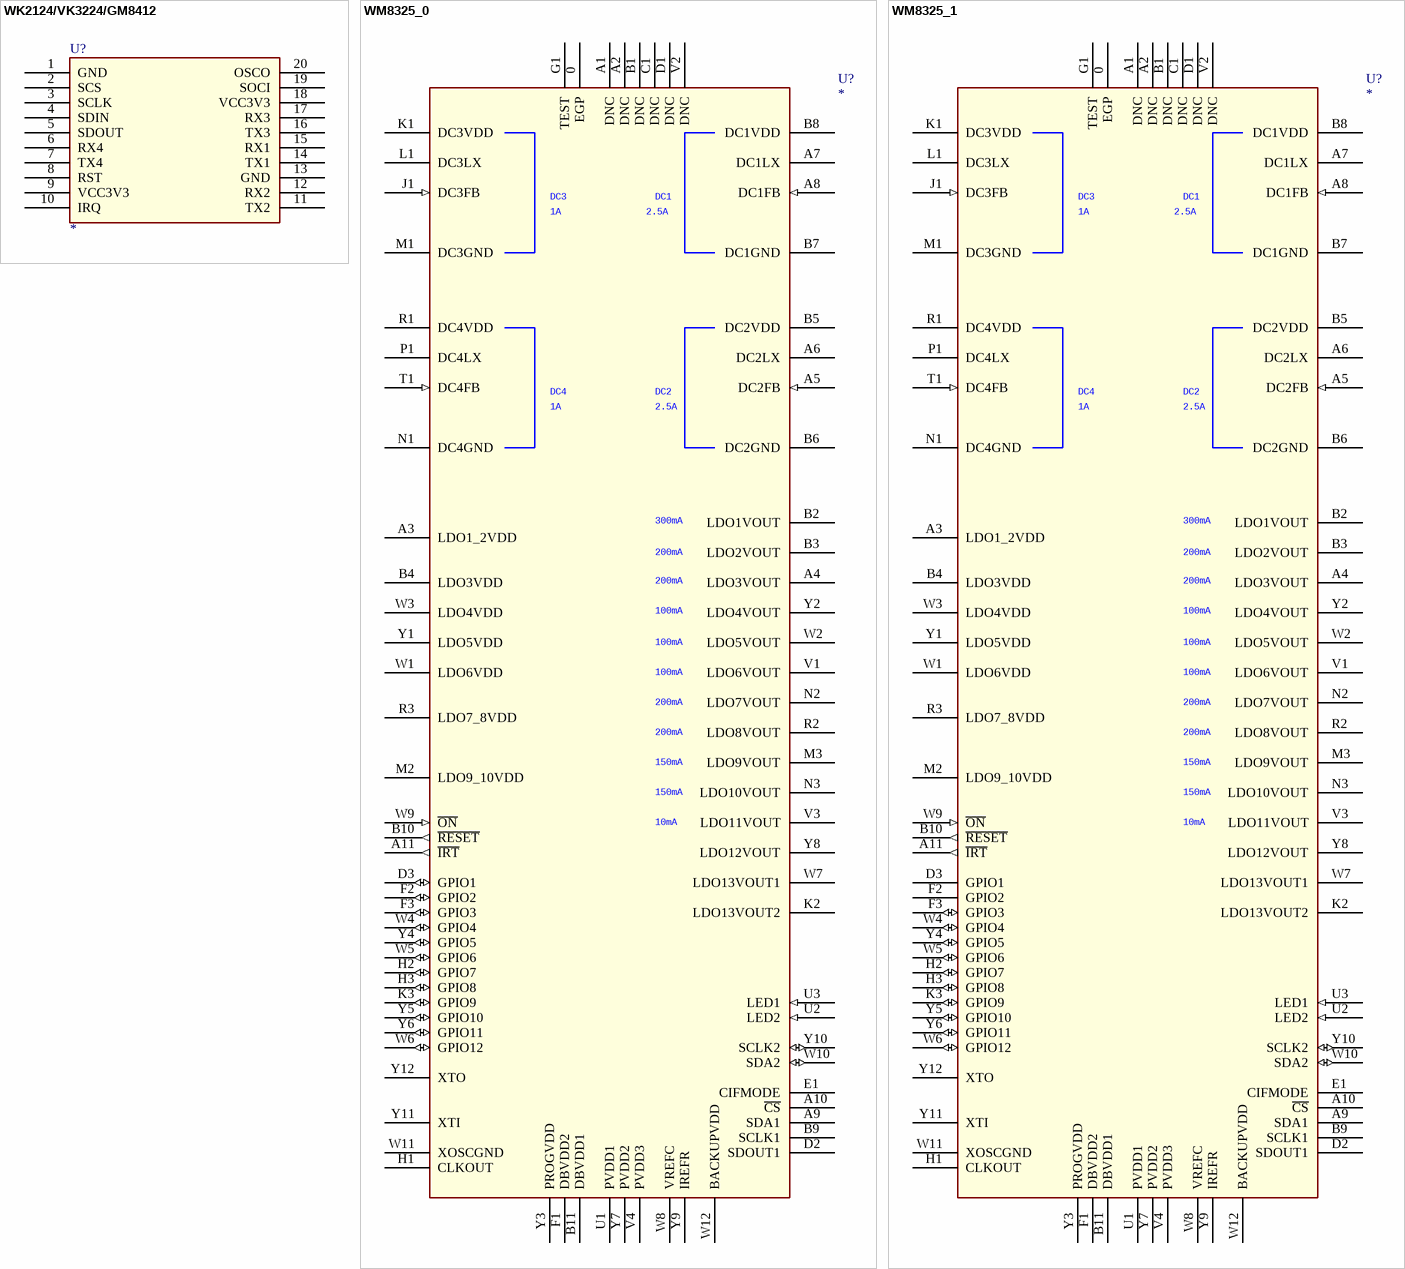
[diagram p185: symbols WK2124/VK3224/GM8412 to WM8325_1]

## WK2124/VK3224/GM8412
designator U?
pins: 1 GND (power), 2 SCS, 3 SCLK, 4 SDIN, 5 SDOUT, 6 RX4, 7 TX4, 8 RST, 9 VCC3V3 (power), 10 IRQ, 11 TX2, 12 RX2, 13 GND (power), 14 TX1, 15 RX1, 16 TX3, 17 RX3, 18 VCC3V3 (power), 19 SOCI, 20 OSCO

## WM8325_0
designator U?
footprint QFN81-8X8
pins: 0 EGP, A1 DNC, A2 DNC, A3 LDO1_2VDD (power), A4 LDO3VOUT (power), A5 DC2FB (in), A6 DC2LX (power), A7 DC1LX (power), A8 DC1FB (in), A9 SDA1, A10 ~{CS}, A11 ~{IRT} (out), B1 DNC, B2 LDO1VOUT (power), B3 LDO2VOUT (power), B4 LDO3VDD (power), B5 DC2VDD (power), B6 DC2GND (power), B7 DC1GND (power), B8 DC1VDD (power), B9 SCLK1, B10 ~{RESET} (out), B11 DBVDD1, C1 DNC, D1 DNC, D2 SDOUT1, D3 GPIO1 (io), E1 CIFMODE, F1 DBVDD2, F2 GPIO2 (io), F3 GPIO3 (io), G1 TEST, H1 CLKOUT, H2 GPIO7 (io), H3 GPIO8 (io), J1 DC3FB (in), K1 DC3VDD (power), K2 LDO13VOUT2 (power), K3 GPIO9 (io), L1 DC3LX (power), M1 DC3GND (power), M2 LDO9_10VDD (power), M3 LDO9VOUT (power), N1 DC4GND (power), N2 LDO7VOUT (power), N3 LDO10VOUT (power), P1 DC4LX (power), R1 DC4VDD (power), R2 LDO8VOUT (power), R3 LDO7_8VDD (power), T1 DC4FB (in), U1 PVDD1, U2 LED2 (in), U3 LED1 (in), V1 LDO6VOUT (power), V2 DNC, V3 LDO11VOUT (power), V4 PVDD3, W1 LDO6VDD (power), W2 LDO5VOUT (power), W3 LDO4VDD (power), W4 GPIO4 (io), W5 GPIO6 (io), W6 GPIO12 (io), W7 LDO13VOUT1 (power), W8 VREFC, W9 ~{ON} (in), W10 SDA2 (io), W11 XOSCGND, W12 BACKUPVDD, Y1 LDO5VDD (power), Y2 LDO4VOUT (power), Y3 PROGVDD, Y4 GPIO5 (io), Y5 GPIO10 (io), Y6 GPIO11 (io), Y7 PVDD2, Y8 LDO12VOUT (power), Y9 IREFR, Y10 SCLK2 (io), Y11 XTI, Y12 XTO

## WM8325_1
designator U?
footprint QFN81-8X8
pins: 0 EGP, A1 DNC, A2 DNC, A3 LDO1_2VDD (power), A4 LDO3VOUT (power), A5 DC2FB (in), A6 DC2LX (power), A7 DC1LX (power), A8 DC1FB (in), A9 SDA1, A10 ~{CS}, A11 ~{IRT} (out), B1 DNC, B2 LDO1VOUT (power), B3 LDO2VOUT (power), B4 LDO3VDD (power), B5 DC2VDD (power), B6 DC2GND (power), B7 DC1GND (power), B8 DC1VDD (power), B9 SCLK1, B10 ~{RESET} (out), B11 DBVDD1, C1 DNC, D1 DNC, D2 SDOUT1, D3 GPIO1, E1 CIFMODE, F1 DBVDD2, F2 GPIO2, F3 GPIO3 (io), G1 TEST, H1 CLKOUT, H2 GPIO7 (io), H3 GPIO8 (io), J1 DC3FB (in), K1 DC3VDD (power), K2 LDO13VOUT2 (power), K3 GPIO9 (io), L1 DC3LX (power), M1 DC3GND (power), M2 LDO9_10VDD (power), M3 LDO9VOUT (power), N1 DC4GND (power), N2 LDO7VOUT (power), N3 LDO10VOUT (power), P1 DC4LX (power), R1 DC4VDD (power), R2 LDO8VOUT (power), R3 LDO7_8VDD (power), T1 DC4FB (in), U1 PVDD1, U2 LED2 (in), U3 LED1 (in), V1 LDO6VOUT (power), V2 DNC, V3 LDO11VOUT (power), V4 PVDD3, W1 LDO6VDD (power), W2 LDO5VOUT (power), W3 LDO4VDD (power), W4 GPIO4 (io), W5 GPIO6 (io), W6 GPIO12 (io), W7 LDO13VOUT1 (power), W8 VREFC, W9 ~{ON} (in), W10 SDA2 (io), W11 XOSCGND, W12 BACKUPVDD, Y1 LDO5VDD (power), Y2 LDO4VOUT (power), Y3 PROGVDD, Y4 GPIO5 (io), Y5 GPIO10 (io), Y6 GPIO11 (io), Y7 PVDD2, Y8 LDO12VOUT (power), Y9 IREFR, Y10 SCLK2 (io), Y11 XTI, Y12 XTO

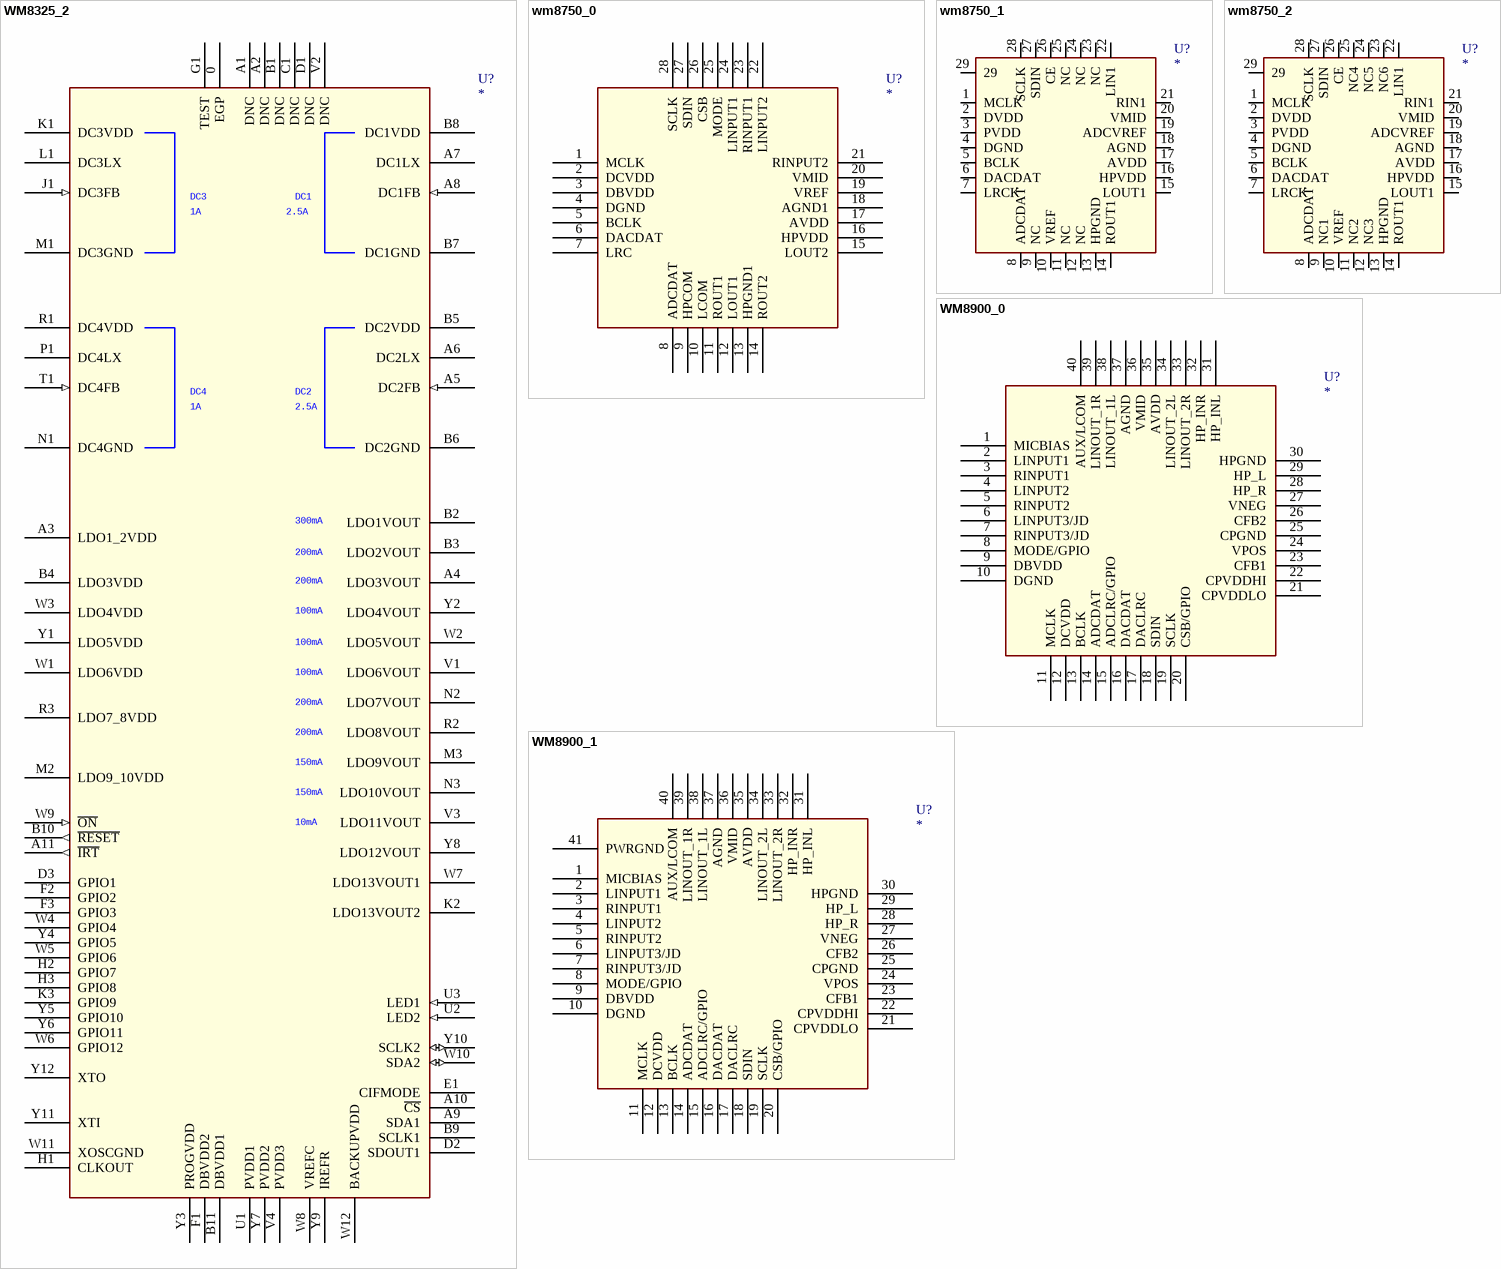
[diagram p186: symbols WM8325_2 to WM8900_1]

## WM8325_2
designator U?
footprint QFN81-8X8
pins: 0 EGP, A1 DNC, A2 DNC, A3 LDO1_2VDD (power), A4 LDO3VOUT (power), A5 DC2FB (in), A6 DC2LX (power), A7 DC1LX (power), A8 DC1FB (in), A9 SDA1, A10 ~{CS}, A11 ~{IRT} (out), B1 DNC, B2 LDO1VOUT (power), B3 LDO2VOUT (power), B4 LDO3VDD (power), B5 DC2VDD (power), B6 DC2GND (power), B7 DC1GND (power), B8 DC1VDD (power), B9 SCLK1, B10 ~{RESET} (out), B11 DBVDD1, C1 DNC, D1 DNC, D2 SDOUT1, D3 GPIO1, E1 CIFMODE, F1 DBVDD2, F2 GPIO2, F3 GPIO3, G1 TEST, H1 CLKOUT, H2 GPIO7, H3 GPIO8, J1 DC3FB (in), K1 DC3VDD (power), K2 LDO13VOUT2 (power), K3 GPIO9, L1 DC3LX (power), M1 DC3GND (power), M2 LDO9_10VDD (power), M3 LDO9VOUT (power), N1 DC4GND (power), N2 LDO7VOUT (power), N3 LDO10VOUT (power), P1 DC4LX (power), R1 DC4VDD (power), R2 LDO8VOUT (power), R3 LDO7_8VDD (power), T1 DC4FB (in), U1 PVDD1, U2 LED2 (in), U3 LED1 (in), V1 LDO6VOUT (power), V2 DNC, V3 LDO11VOUT (power), V4 PVDD3, W1 LDO6VDD (power), W2 LDO5VOUT (power), W3 LDO4VDD (power), W4 GPIO4, W5 GPIO6, W6 GPIO12, W7 LDO13VOUT1 (power), W8 VREFC, W9 ~{ON} (in), W10 SDA2 (io), W11 XOSCGND, W12 BACKUPVDD, Y1 LDO5VDD (power), Y2 LDO4VOUT (power), Y3 PROGVDD, Y4 GPIO5, Y5 GPIO10, Y6 GPIO11, Y7 PVDD2, Y8 LDO12VOUT (power), Y9 IREFR, Y10 SCLK2 (io), Y11 XTI, Y12 XTO

## wm8750_0
designator U?
pins: 1 MCLK, 2 DCVDD, 3 DBVDD, 4 DGND, 5 BCLK, 6 DACDAT, 7 LRC, 8 ADCDAT, 9 HPCOM, 10 LCOM, 11 ROUT1, 12 LOUT1, 13 HPGND1, 14 ROUT2, 15 LOUT2, 16 HPVDD, 17 AVDD, 18 AGND1, 19 VREF, 20 VMID, 21 RINPUT2, 22 LINPUT2, 23 RINPUT1, 24 LINPUT1, 25 MODE, 26 CSB, 27 SDIN, 28 SCLK

## wm8750_1
designator U?
pins: 1 MCLK, 2 DVDD, 3 PVDD, 4 DGND, 5 BCLK, 6 DACDAT, 7 LRCK, 8 ADCDAT, 9 NC, 10 VREF, 11 NC, 12 NC, 13 HPGND, 14 ROUT1, 15 LOUT1, 16 HPVDD, 17 AVDD, 18 AGND, 19 ADCVREF, 20 VMID, 21 RIN1, 22 LIN1, 23 NC, 24 NC, 25 NC, 26 CE, 27 SDIN, 28 SCLK, 29

## wm8750_2
designator U?
pins: 1 MCLK, 2 DVDD, 3 PVDD, 4 DGND, 5 BCLK, 6 DACDAT, 7 LRCK, 8 ADCDAT, 9 NC1, 10 VREF, 11 NC2, 12 NC3, 13 HPGND, 14 ROUT1, 15 LOUT1, 16 HPVDD, 17 AVDD, 18 AGND, 19 ADCVREF, 20 VMID, 21 RIN1, 22 LIN1, 23 NC6, 24 NC5, 25 NC4, 26 CE, 27 SDIN, 28 SCLK, 29

## WM8900_0
designator U?
footprint QFN40
pins: 1 MICBIAS, 2 LINPUT1, 3 RINPUT1, 4 LINPUT2, 5 RINPUT2, 6 LINPUT3/JD, 7 RINPUT3/JD, 8 MODE/GPIO, 9 DBVDD, 10 DGND, 11 MCLK, 12 DCVDD, 13 BCLK, 14 ADCDAT, 15 ADCLRC/GPIO, 16 DACDAT, 17 DACLRC, 18 SDIN, 19 SCLK, 20 CSB/GPIO, 21 CPVDDLO, 22 CPVDDHI, 23 CFB1, 24 VPOS, 25 CPGND, 26 CFB2, 27 VNEG, 28 HP_R, 29 HP_L, 30 HPGND, 31 HP_INL, 32 HP_INR, 33 LINOUT_2R, 34 LINOUT_2L, 35 AVDD, 36 VMID, 37 AGND, 38 LINOUT_1L, 39 LINOUT_1R, 40 AUX/LCOM

## WM8900_1
designator U?
footprint QFN40
pins: 1 MICBIAS, 2 LINPUT1, 3 RINPUT1, 4 LINPUT2, 5 RINPUT2, 6 LINPUT3/JD, 7 RINPUT3/JD, 8 MODE/GPIO, 9 DBVDD, 10 DGND, 11 MCLK, 12 DCVDD, 13 BCLK, 14 ADCDAT, 15 ADCLRC/GPIO, 16 DACDAT, 17 DACLRC, 18 SDIN, 19 SCLK, 20 CSB/GPIO, 21 CPVDDLO, 22 CPVDDHI, 23 CFB1, 24 VPOS, 25 CPGND, 26 CFB2, 27 VNEG, 28 HP_R, 29 HP_L, 30 HPGND, 31 HP_INL, 32 HP_INR, 33 LINOUT_2R, 34 LINOUT_2L, 35 AVDD, 36 VMID, 37 AGND, 38 LINOUT_1L, 39 LINOUT_1R, 40 AUX/LCOM, 41 PWRGND

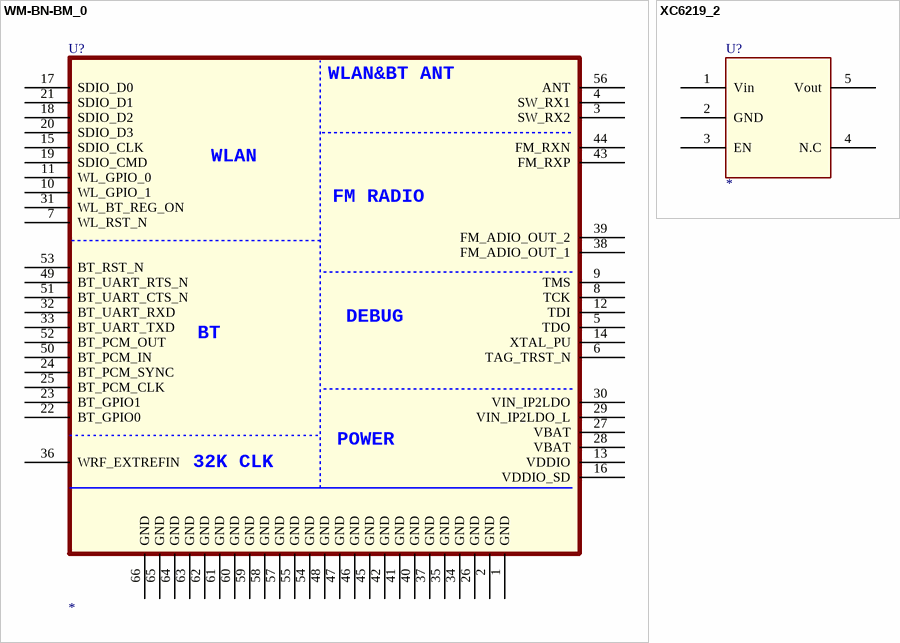
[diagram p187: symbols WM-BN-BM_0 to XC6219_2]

## WM-BN-BM_0
designator U?
footprint LGA66
pins: 1 GND, 2 GND, 3 SW_RX2, 4 SW_RX1, 5 TDO, 6 TAG_TRST_N, 7 WL_RST_N, 8 TCK, 9 TMS, 10 WL_GPIO_1, 11 WL_GPIO_0, 12 TDI, 13 VDDIO, 14 XTAL_PU, 15 SDIO_CLK, 16 VDDIO_SD, 17 SDIO_D0, 18 SDIO_D2, 19 SDIO_CMD, 20 SDIO_D3, 21 SDIO_D1, 22 BT_GPIO0, 23 BT_GPIO1, 24 BT_PCM_SYNC, 25 BT_PCM_CLK, 26 GND, 27 VBAT, 28 VBAT, 29 VIN_IP2LDO_L, 30 VIN_IP2LDO, 31 WL_BT_REG_ON, 32 BT_UART_RXD, 33 BT_UART_TXD, 34 GND, 35 GND, 36 WRF_EXTREFIN, 37 GND, 38 FM_ADIO_OUT_1, 39 FM_ADIO_OUT_2, 40 GND, 41 GND, 42 GND, 43 FM_RXP, 44 FM_RXN, 45 GND, 46 GND, 47 GND, 48 GND, 49 BT_UART_RTS_N, 50 BT_PCM_IN, 51 BT_UART_CTS_N, 52 BT_PCM_OUT, 53 BT_RST_N, 54 GND, 55 GND, 56 ANT, 57 GND, 58 GND, 59 GND, 60 GND, 61 GND, 62 GND, 63 GND, 64 GND, 65 GND, 66 GND

## XC6219_2
designator U?
pins: 1 Vin, 2 GND, 3 EN, 4 N.C, 5 Vout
